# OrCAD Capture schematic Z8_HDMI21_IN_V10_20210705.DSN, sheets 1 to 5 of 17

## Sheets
1 PAGE06-HDMI21 IN: size Custom
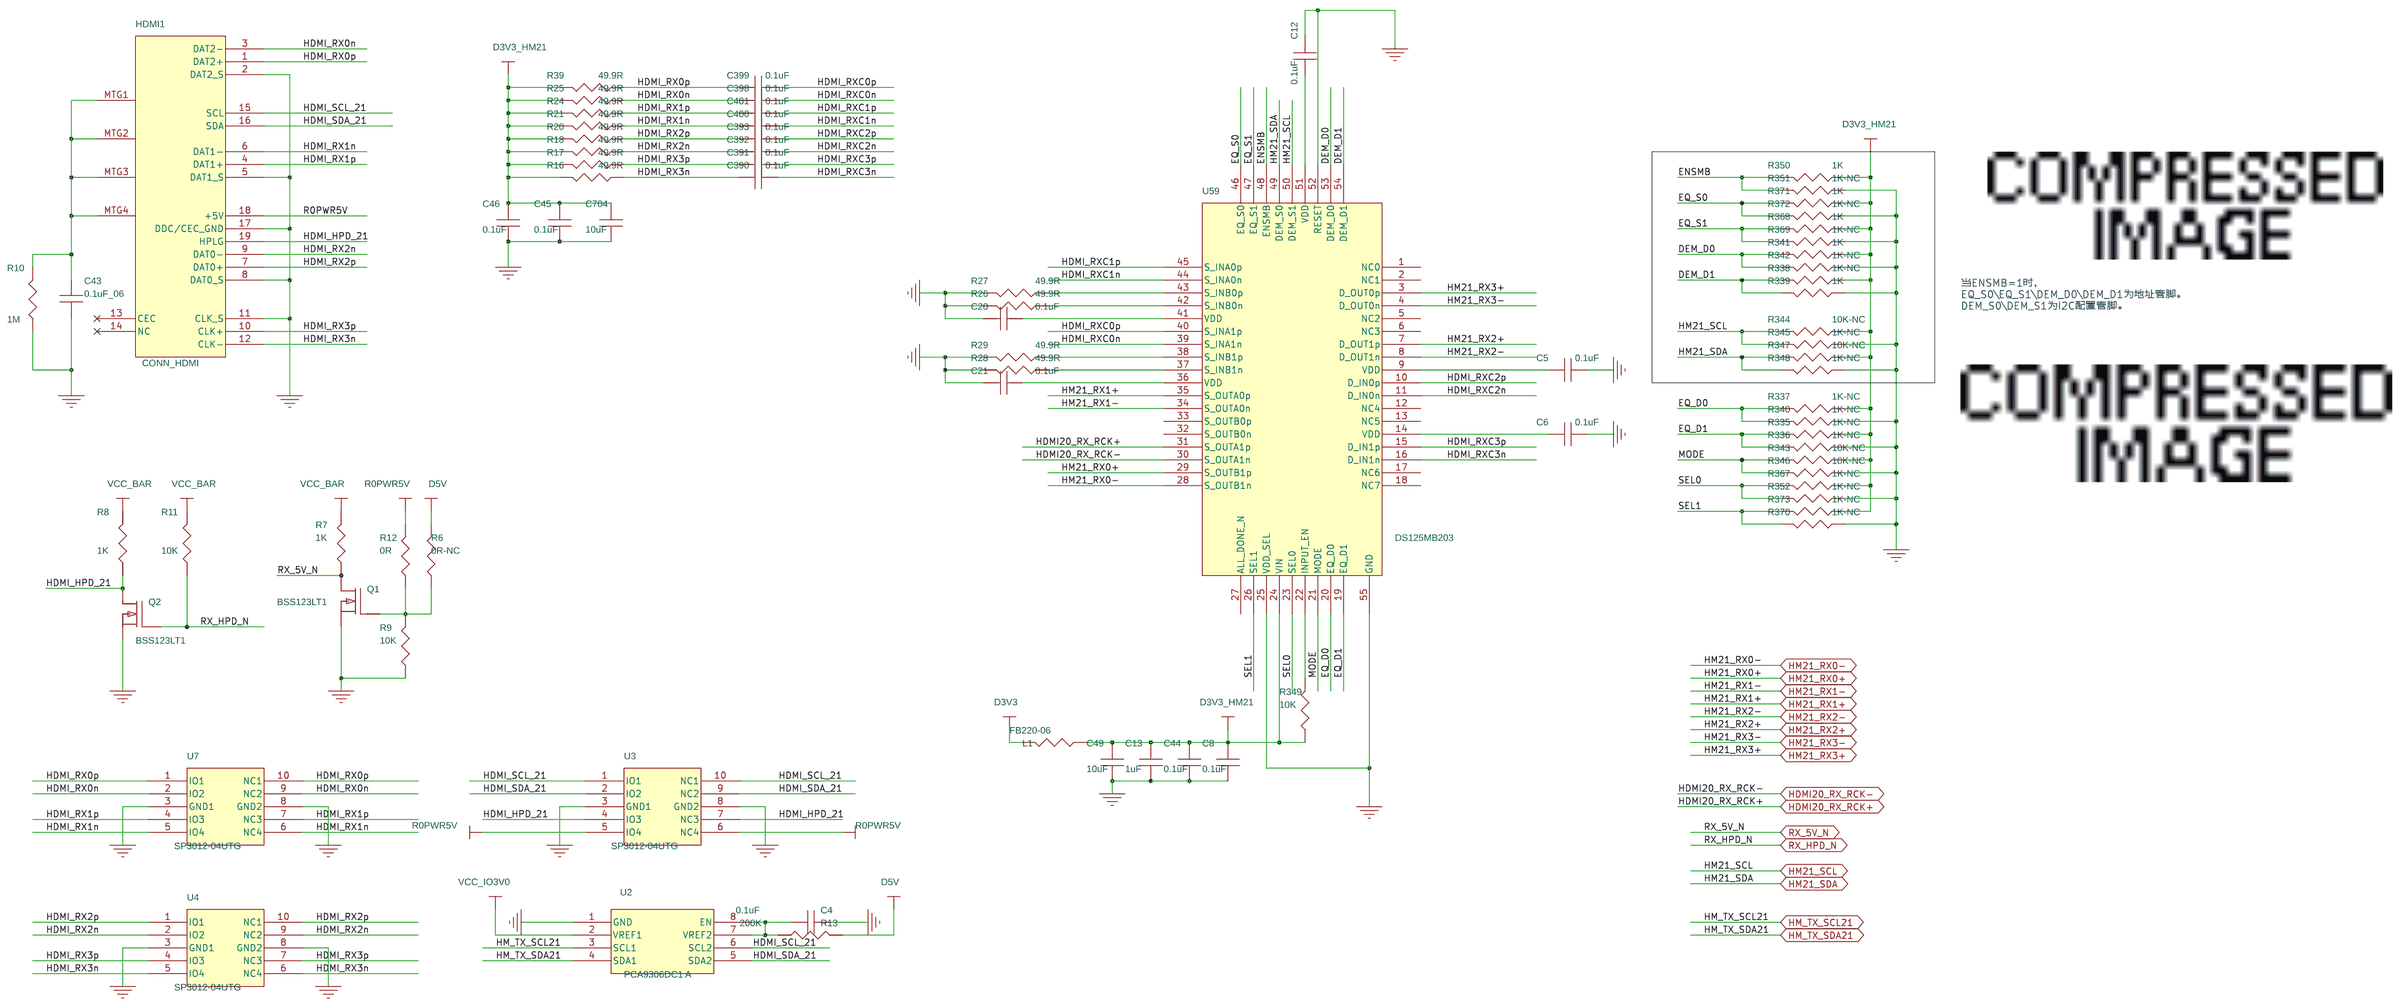
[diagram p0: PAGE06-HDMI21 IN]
2 PAGE10-HDMI20 OUT4: size Custom
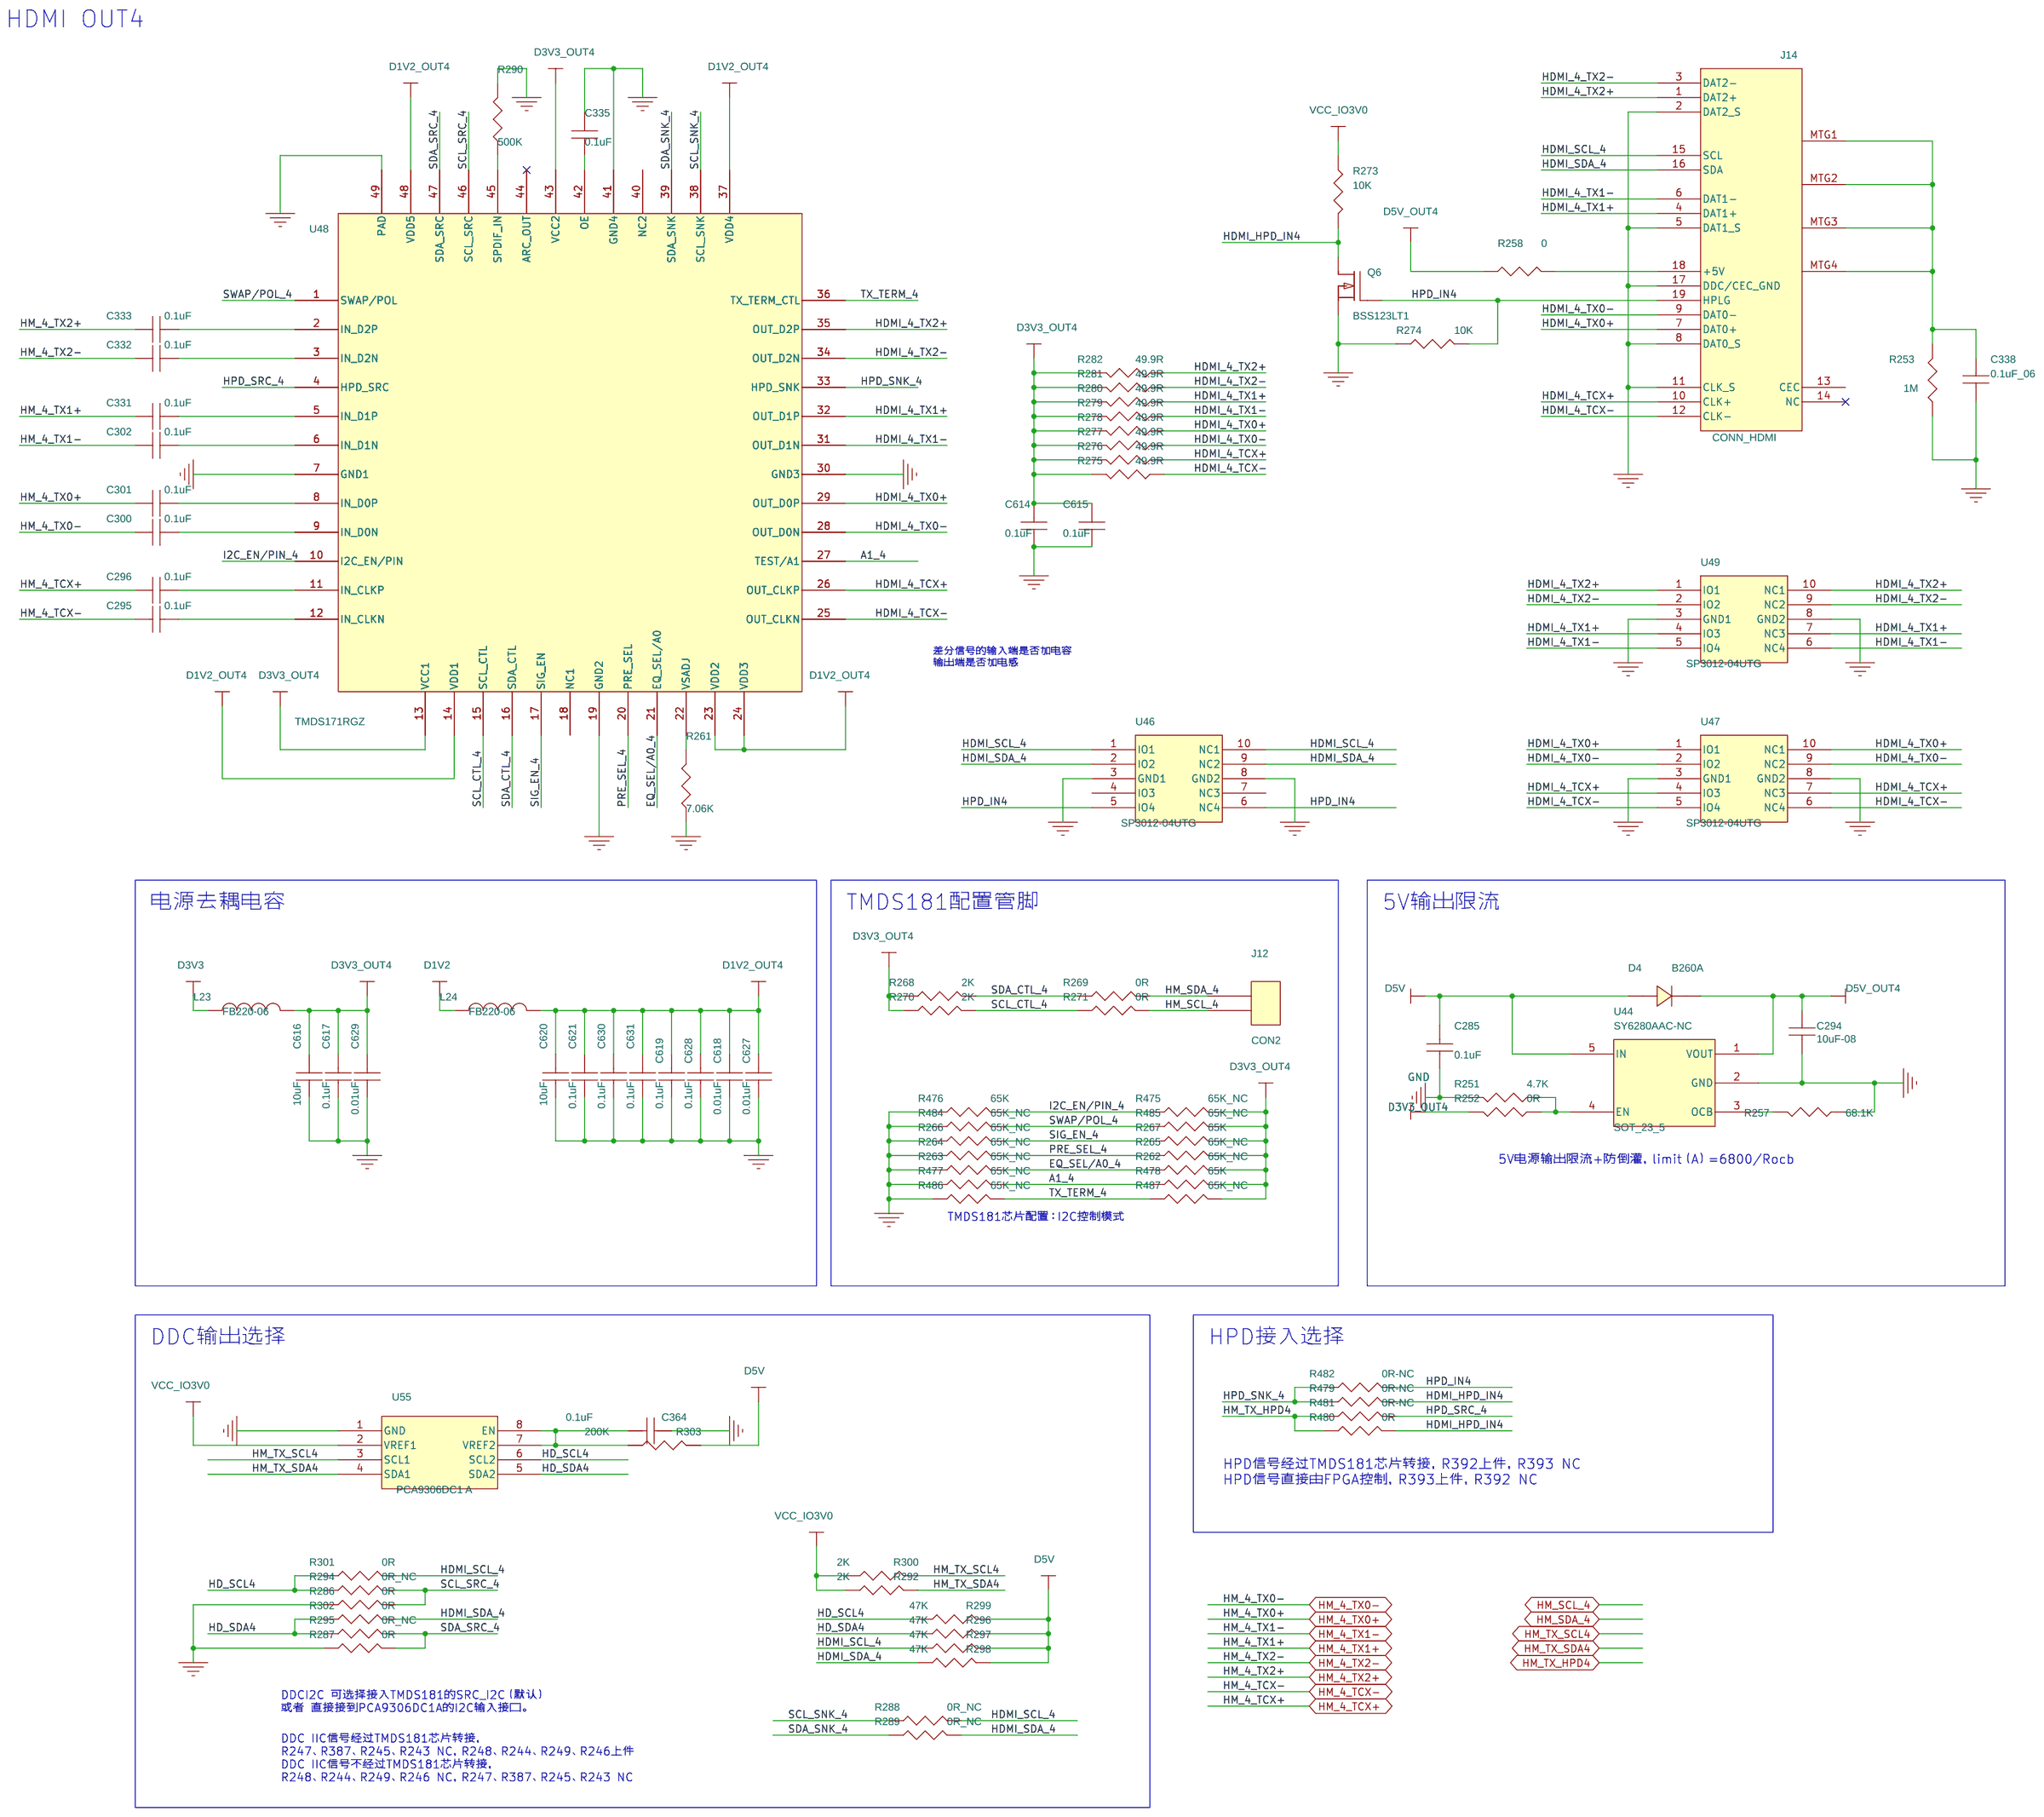
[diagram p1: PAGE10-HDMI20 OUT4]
3 PAGE09-HDMI20 OUT3: size Custom
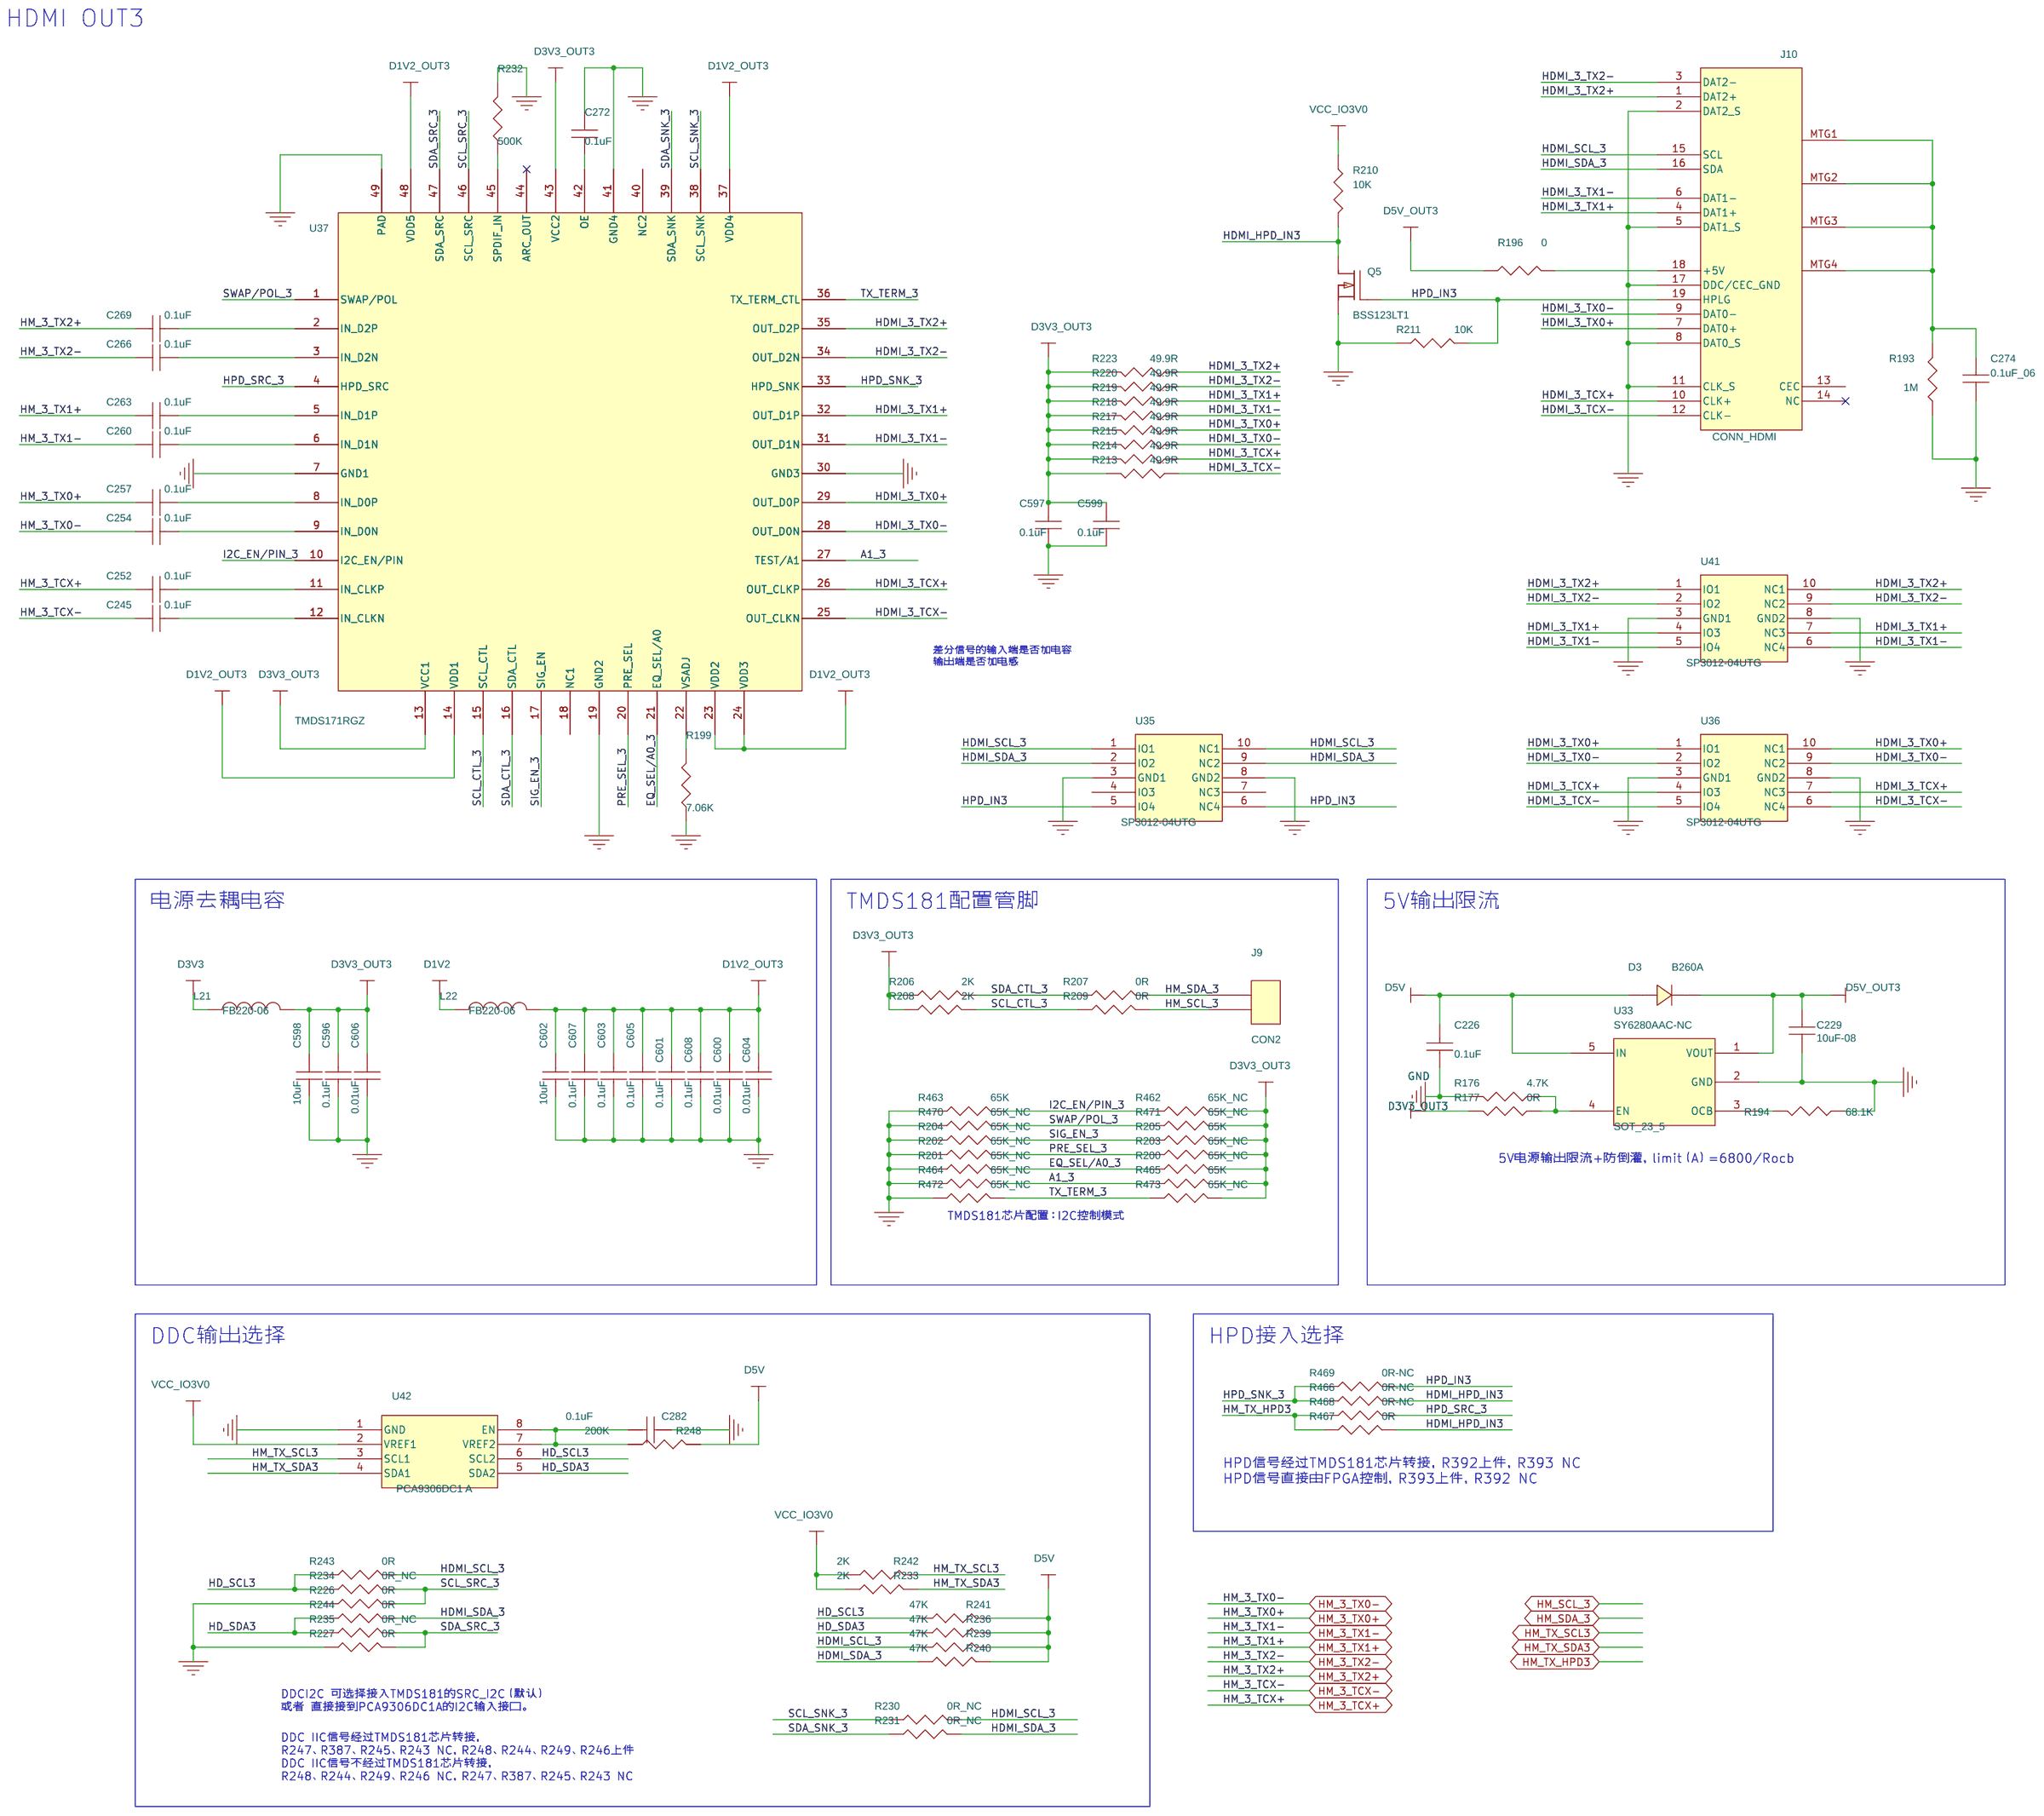
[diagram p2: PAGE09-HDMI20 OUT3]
4 PAGE12-10AX032-(2K&2J): size C
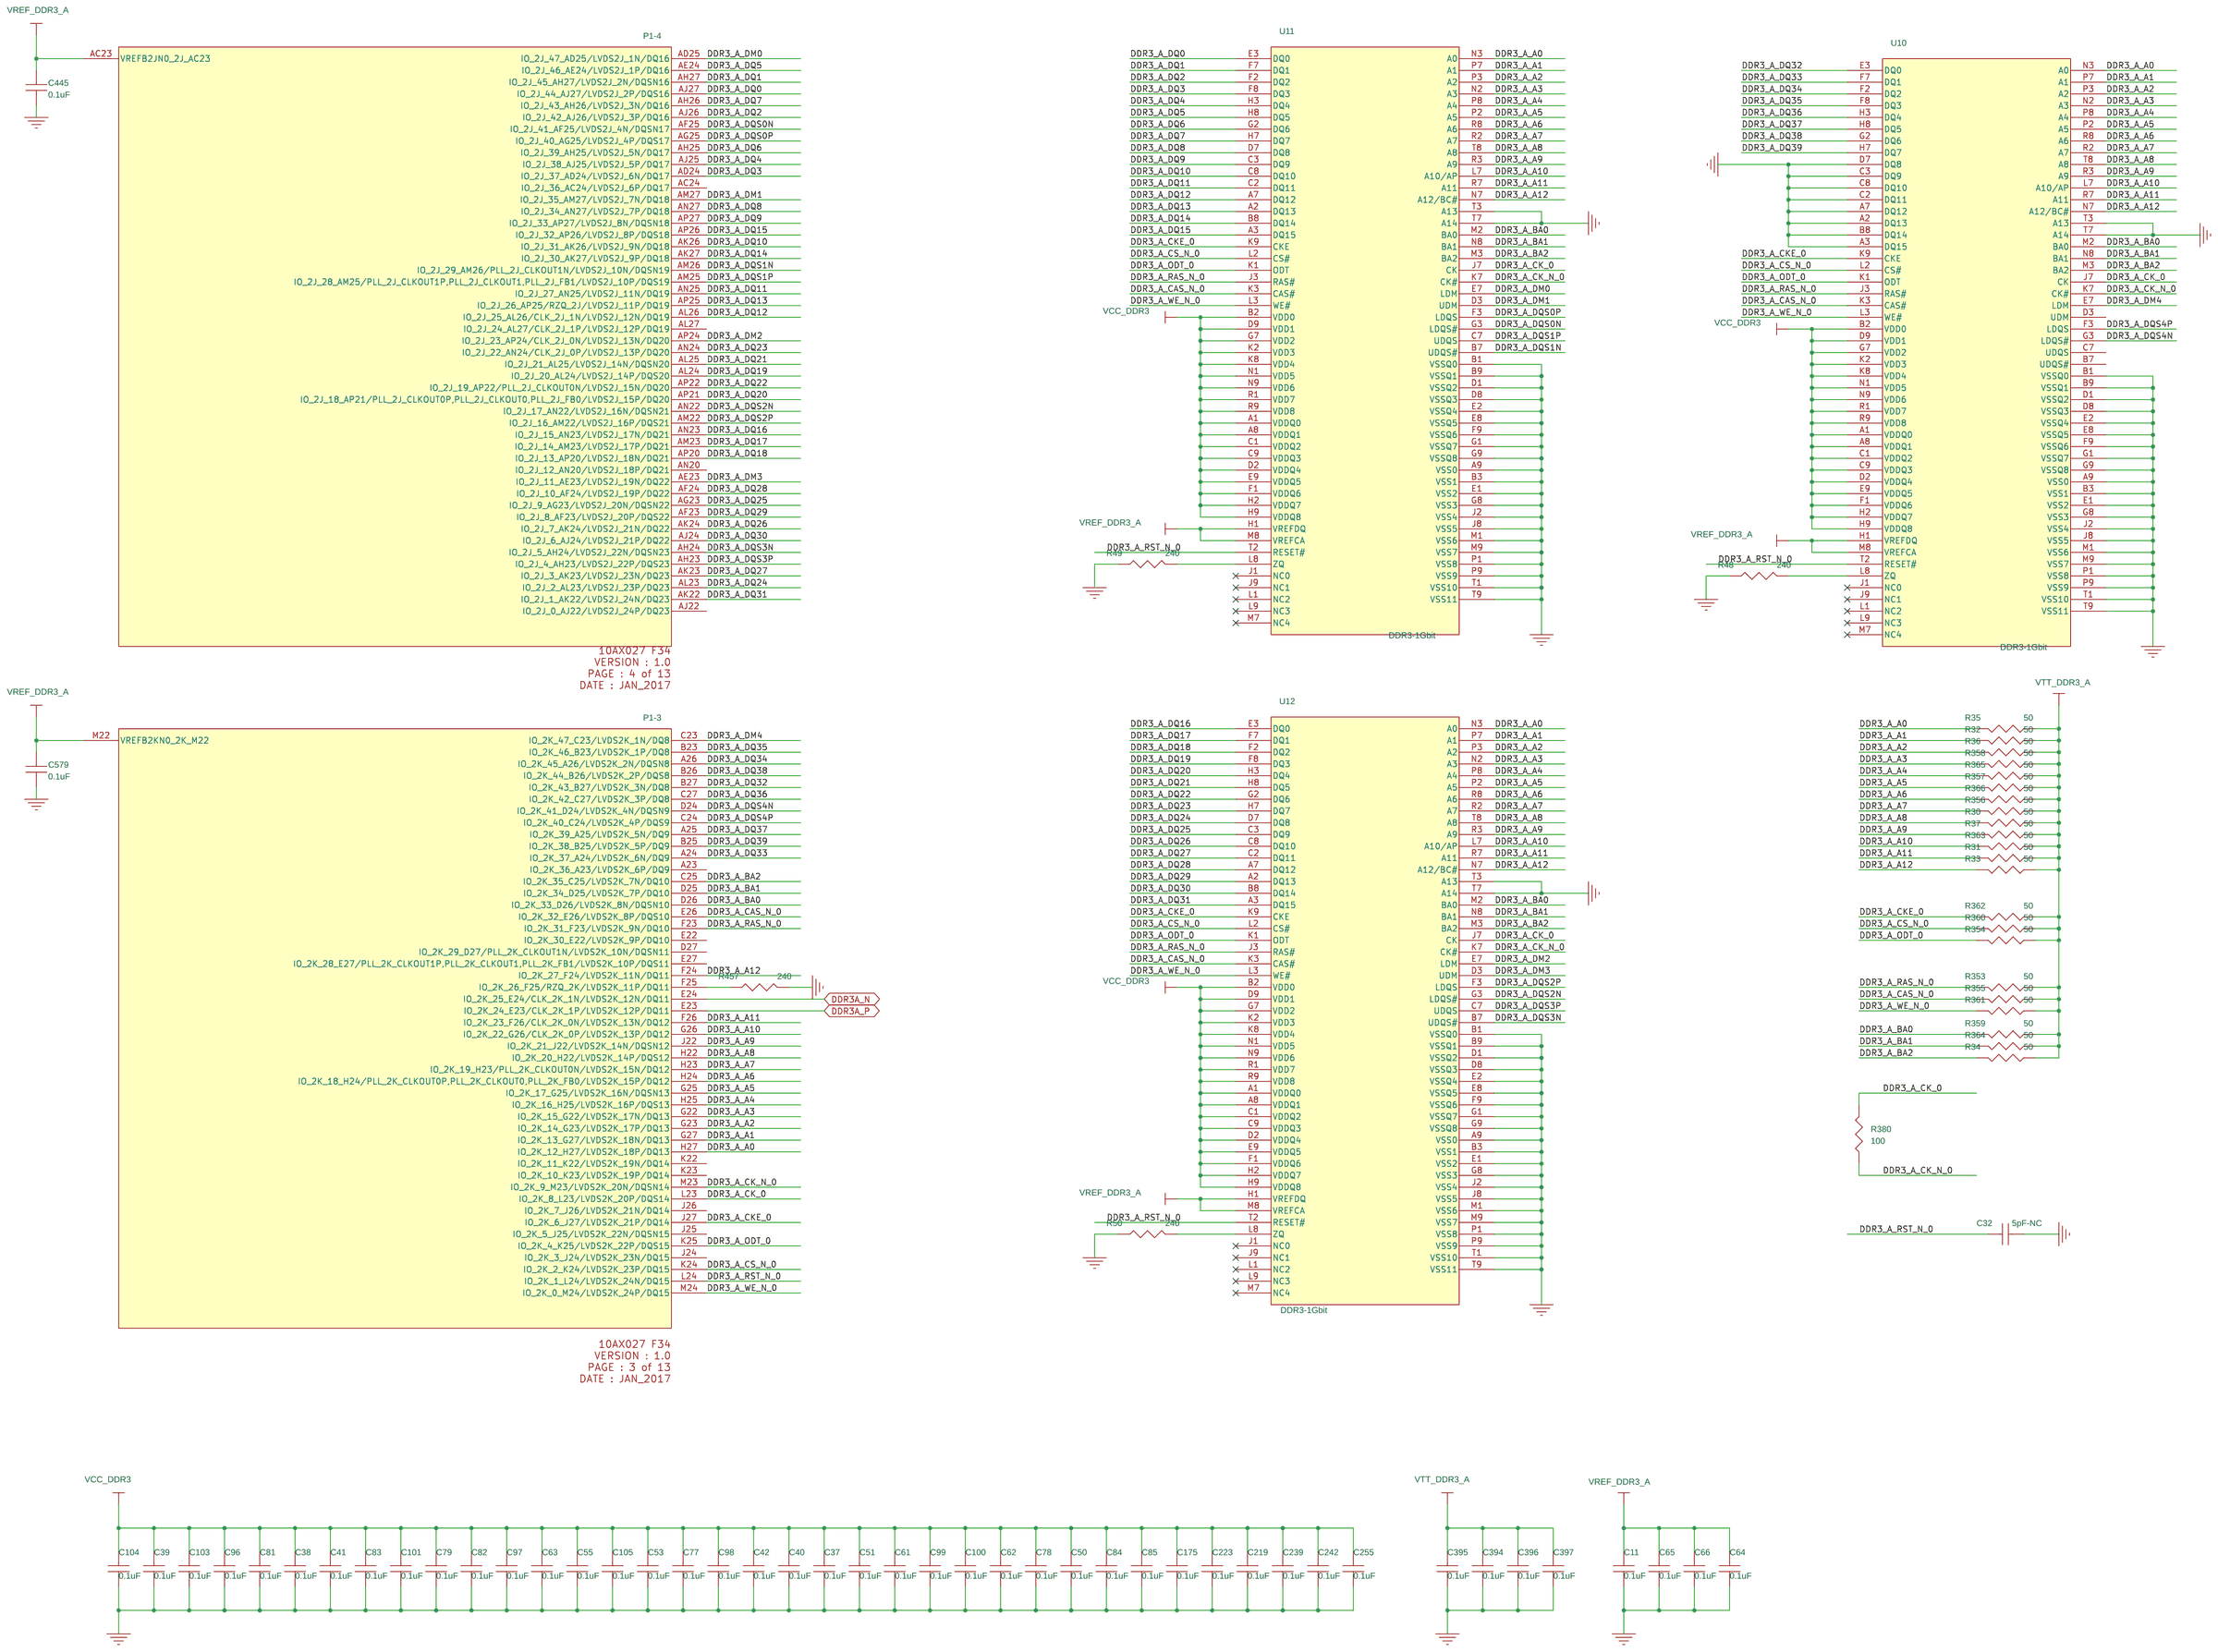
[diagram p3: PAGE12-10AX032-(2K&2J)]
5 PAGE11-10AX032-(GX): size D
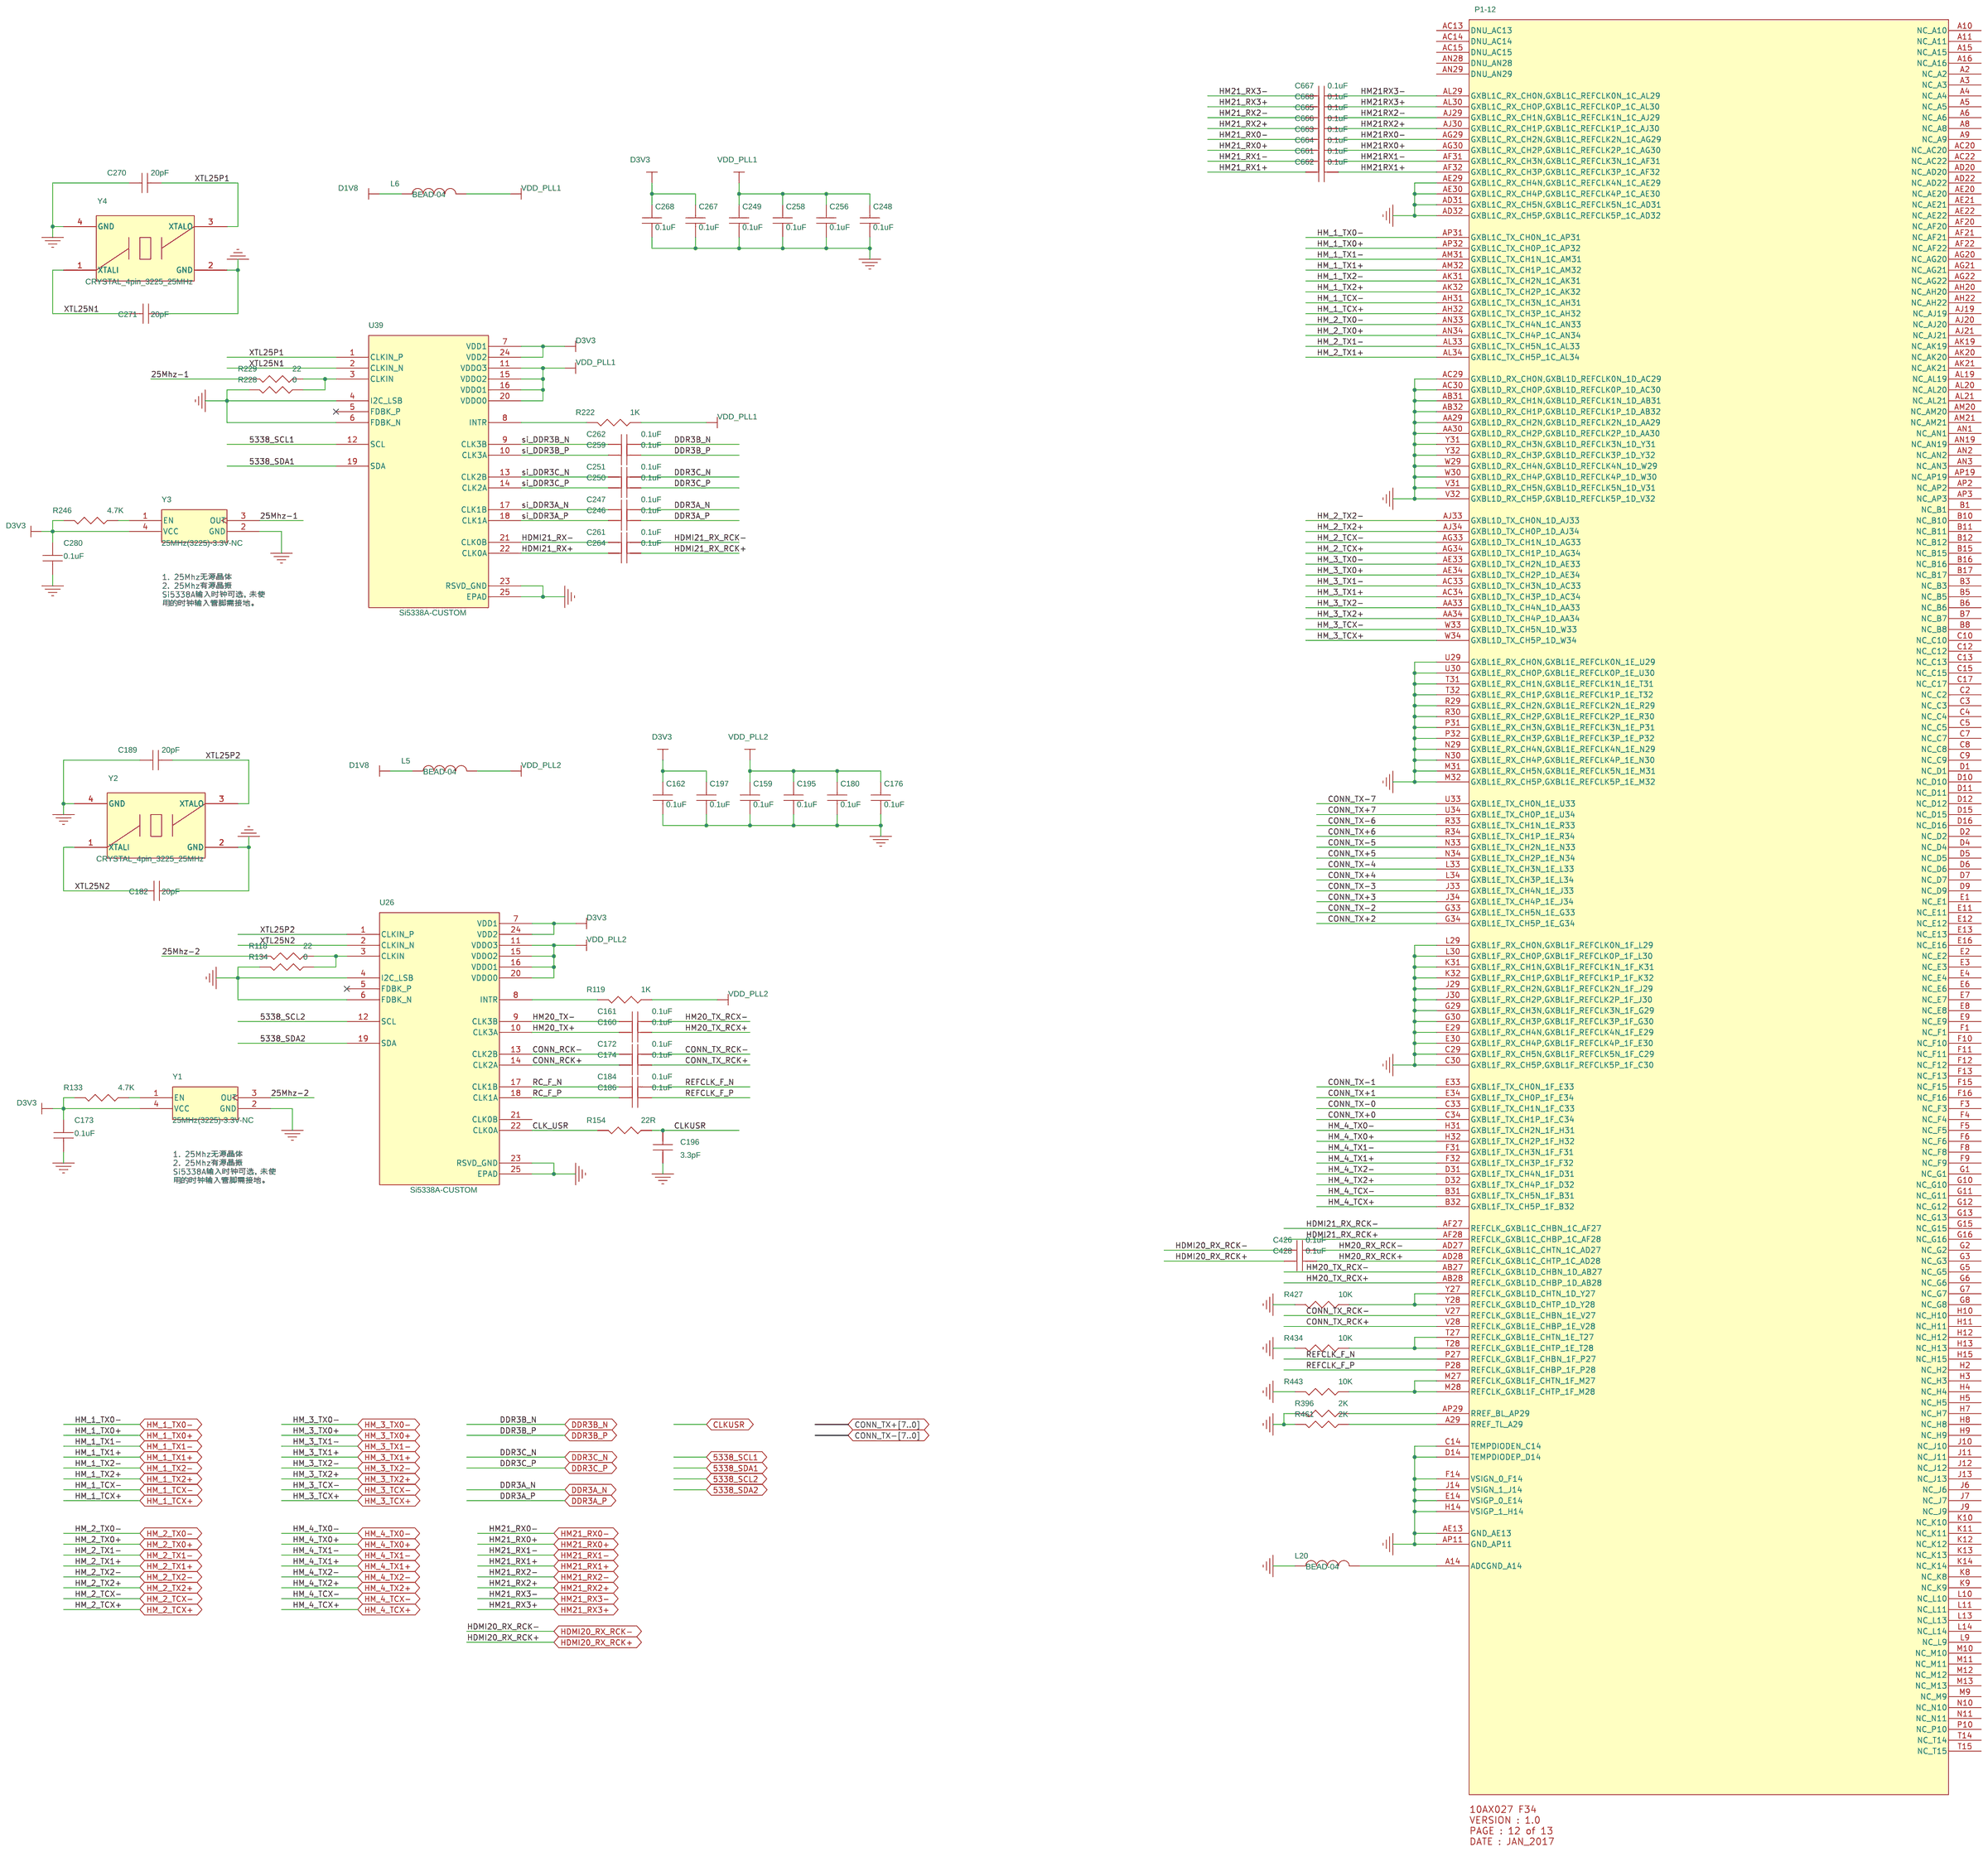
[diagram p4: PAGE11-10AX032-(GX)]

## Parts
sheet PAGE06-HDMI21 IN
C4  0.1uF  [C0402]
C5  0.1uF  [C0402]
C6  0.1uF  [C0402]
C8  0.1uF  [C0402]
C12  0.1uF  [C0402]
C13  1uF  [C0402]
C20  0.1uF  [C0402]
C21  0.1uF  [C0402]
C43  0.1uF_06  [C0402]
C44  0.1uF  [C0402]
C45  0.1uF  [C0402]
C46  0.1uF  [C0402]
C49  10uF  [C0402]
C390  0.1uF  [C0402-8]
C391  0.1uF  [C0402-8]
C392  0.1uF  [C0402-8]
C393  0.1uF  [C0402-8]
C398  0.1uF  [C0402-8]
C399  0.1uF  [C0402-8]
C400  0.1uF  [C0402-8]
C401  0.1uF  [C0402-8]
C704  10uF  [C0402]
HDMI1  CONN_HDMI  [hdmi]
L1  FB220-06  [R0603]
Q1  BSS123LT1  [SOT-23]
Q2  BSS123LT1  [SOT-23]
R6  0R-NC  [R0402]
R7  1K  [R0402]
R8  1K  [R0402]
R9  10K  [R0402]
R10  1M  [R0402]
R11  10K  [R0402]
R12  0R  [R0402]
R13  200K  [R0402]
R16  49.9R  [R0402]
R17  49.9R  [R0402]
R18  49.9R  [R0402]
R20  49.9R  [R0402]
R21  49.9R  [R0402]
R24  49.9R  [R0402]
R25  49.9R  [R0402]
R26  49.9R  [R0402]
R27  49.9R  [R0402]
R28  49.9R  [R0402]
R29  49.9R  [R0402]
R39  49.9R  [R0402]
R335  1K-NC  [R0402]
R336  1K-NC  [R0402]
R337  1K-NC  [R0402]
R338  1K-NC  [R0402]
R339  1K  [R0402]
R340  1K-NC  [R0402]
R341  1K  [R0402]
R342  1K-NC  [R0402]
R343  10K-NC  [R0402]
R344  10K-NC  [R0402]
R345  1K-NC  [R0402]
R346  10K-NC  [R0402]
R347  10K-NC  [R0402]
R348  1K-NC  [R0402]
R349  10K  [R0402]
R350  1K  [R0402]
R351  1K-NC  [R0402]
R352  1K-NC  [R0402]
R367  1K-NC  [R0402]
R368  1K  [R0402]
R369  1K-NC  [R0402]
R370  1K-NC  [R0402]
R371  1K  [R0402]
R372  1K-NC  [R0402]
R373  1K-NC  [R0402]
U2  PCA9306DC1 A  [SOIC8_E0D65_4D55XE3D15]
U3  SP3012-04UTG  [uDFN-10]
U4  SP3012-04UTG  [uDFN-10]
U7  SP3012-04UTG  [uDFN-10]
U59  DS125MB203  [DS125MB203]
sheet PAGE09-HDMI20 OUT3
C226  0.1uF  [C0402]
C229  10uF-08  [C0805]
C245  0.1uF  [C0402]
C252  0.1uF  [C0402]
C254  0.1uF  [C0402]
C257  0.1uF  [C0402]
C260  0.1uF  [C0402]
C263  0.1uF  [C0402]
C266  0.1uF  [C0402]
C269  0.1uF  [C0402]
C272  0.1uF  [C0402]
C274  0.1uF_06  [C0402]
C282  0.1uF  [C0402]
C596  0.1uF  [C0402]
C597  0.1uF  [C0402]
C598  10uF  [C0402]
C599  0.1uF  [C0402]
C600  0.01uF  [C0402]
C601  0.1uF  [C0402]
C602  10uF  [C0402]
C603  0.1uF  [C0402]
C604  0.01uF  [C0402]
C605  0.1uF  [C0402]
C606  0.01uF  [C0402]
C607  0.1uF  [C0402]
C608  0.1uF  [C0402]
D3  B260A  [SMA_DIODES]
J9  CON2  [CON2]
J10  CONN_HDMI  [hdmi]
L21  FB220-06  [my_0603_res]
L22  FB220-06  [my_0603_res]
Q5  BSS123LT1  [SOT-23]
R176  4.7K  [R0402]
R177  0R  [R0402]
R193  1M  [R0402]
R194  68.1K  [R0402]
R196  0  [R0402]
R199  7.06K  [R0402]
R200  65K_NC  [R0402]
R201  65K_NC  [R0402]
R202  65K_NC  [R0402]
R203  65K_NC  [R0402]
R204  65K_NC  [R0402]
R205  65K  [R0402]
R206  2K  [R0402]
R207  0R  [R0402]
R208  2K  [R0402]
R209  0R  [R0402]
R210  10K  [R0402]
R211  10K  [R0402]
R213  49.9R  [R0402]
R214  49.9R  [R0402]
R215  49.9R  [R0402]
R217  49.9R  [R0402]
R218  49.9R  [R0402]
R219  49.9R  [R0402]
R220  49.9R  [R0402]
R223  49.9R  [R0402]
R226  0R  [R0402]
R227  0R  [R0402]
R230  0R_NC  [R0402]
R231  0R_NC  [R0402]
R232  500K  [R0402]
R233  2K  [R0402]
R234  0R_NC  [R0402]
R235  0R_NC  [R0402]
R236  47K  [R0402]
R239  47K  [R0402]
R240  47K  [R0402]
R241  47K  [R0402]
R242  2K  [R0402]
R243  0R  [R0402]
R244  0R  [R0402]
R248  200K  [R0402]
R462  65K_NC  [R0402]
R463  65K  [R0402]
R464  65K_NC  [R0402]
R465  65K  [R0402]
R466  0R-NC  [R0402]
R467  0R  [R0402]
R468  0R-NC  [R0402]
R469  0R-NC  [R0402]
R470  65K_NC  [R0402]
R471  65K_NC  [R0402]
R472  65K_NC  [R0402]
R473  65K_NC  [R0402]
U33  SY6280AAC-NC  [SOT_23_5]
U35  SP3012-04UTG  [uDFN-10]
U36  SP3012-04UTG  [uDFN-10]
U37  TMDS171RGZ  [QFN48_TMDS181]
U41  SP3012-04UTG  [uDFN-10]
U42  PCA9306DC1 A  [SOIC8_E0D65_4D55XE3D15]
sheet PAGE10-HDMI20 OUT4
C285  0.1uF  [C0402]
C294  10uF-08  [C0805]
C295  0.1uF  [C0402]
C296  0.1uF  [C0402]
C300  0.1uF  [C0402]
C301  0.1uF  [C0402]
C302  0.1uF  [C0402]
C331  0.1uF  [C0402]
C332  0.1uF  [C0402]
C333  0.1uF  [C0402]
C335  0.1uF  [C0402]
C338  0.1uF_06  [C0402]
C364  0.1uF  [C0402]
C614  0.1uF  [C0402]
C615  0.1uF  [C0402]
C616  10uF  [C0402]
C617  0.1uF  [C0402]
C618  0.01uF  [C0402]
C619  0.1uF  [C0402]
C620  10uF  [C0402]
C621  0.1uF  [C0402]
C627  0.01uF  [C0402]
C628  0.1uF  [C0402]
C629  0.01uF  [C0402]
C630  0.1uF  [C0402]
C631  0.1uF  [C0402]
D4  B260A  [SMA_DIODES]
J12  CON2  [CON2]
J14  CONN_HDMI  [hdmi]
L23  FB220-06  [my_0603_res]
L24  FB220-06  [my_0603_res]
Q6  BSS123LT1  [SOT-23]
R251  4.7K  [R0402]
R252  0R  [R0402]
R253  1M  [R0402]
R257  68.1K  [R0402]
R258  0  [R0402]
R261  7.06K  [R0402]
R262  65K_NC  [R0402]
R263  65K_NC  [R0402]
R264  65K_NC  [R0402]
R265  65K_NC  [R0402]
R266  65K_NC  [R0402]
R267  65K  [R0402]
R268  2K  [R0402]
R269  0R  [R0402]
R270  2K  [R0402]
R271  0R  [R0402]
R273  10K  [R0402]
R274  10K  [R0402]
R275  49.9R  [R0402]
R276  49.9R  [R0402]
R277  49.9R  [R0402]
R278  49.9R  [R0402]
R279  49.9R  [R0402]
R280  49.9R  [R0402]
R281  49.9R  [R0402]
R282  49.9R  [R0402]
R286  0R  [R0402]
R287  0R  [R0402]
R288  0R_NC  [R0402]
R289  0R_NC  [R0402]
R290  500K  [R0402]
R292  2K  [R0402]
R294  0R_NC  [R0402]
R295  0R_NC  [R0402]
R296  47K  [R0402]
R297  47K  [R0402]
R298  47K  [R0402]
R299  47K  [R0402]
R300  2K  [R0402]
R301  0R  [R0402]
R302  0R  [R0402]
R303  200K  [R0402]
R475  65K_NC  [R0402]
R476  65K  [R0402]
R477  65K_NC  [R0402]
R478  65K  [R0402]
R479  0R-NC  [R0402]
R480  0R  [R0402]
R481  0R-NC  [R0402]
R482  0R-NC  [R0402]
R484  65K_NC  [R0402]
R485  65K_NC  [R0402]
R486  65K_NC  [R0402]
R487  65K_NC  [R0402]
U44  SY6280AAC-NC  [SOT_23_5]
U46  SP3012-04UTG  [uDFN-10]
U47  SP3012-04UTG  [uDFN-10]
U48  TMDS171RGZ  [QFN48_TMDS181]
U49  SP3012-04UTG  [uDFN-10]
U55  PCA9306DC1 A  [SOIC8_E0D65_4D55XE3D15]
sheet PAGE11-10AX032-(GX)
C159  0.1uF  [C0402]
C160  0.1uF  [C0402]
C161  0.1uF  [C0402]
C162  0.1uF  [C0402]
C172  0.1uF  [C0402]
C173  0.1uF  [C0402]
C174  0.1uF  [C0402]
C176  0.1uF  [C0402]
C180  0.1uF  [C0402]
C182  20pF  [C0402]
C184  0.1uF  [C0402]
C186  0.1uF  [C0402]
C189  20pF  [C0402]
C195  0.1uF  [C0402]
C196  3.3pF  [C0402]
C197  0.1uF  [C0402]
C246  0.1uF  [C0402]
C247  0.1uF  [C0402]
C248  0.1uF  [C0402]
C249  0.1uF  [C0402]
C250  0.1uF  [C0402]
C251  0.1uF  [C0402]
C256  0.1uF  [C0402]
C258  0.1uF  [C0402]
C259  0.1uF  [C0402]
C261  0.1uF  [C0402]
C262  0.1uF  [C0402]
C264  0.1uF  [C0402]
C267  0.1uF  [C0402]
C268  0.1uF  [C0402]
C270  20pF  [C0402]
C271  20pF  [C0402]
C280  0.1uF  [C0402]
C426  0.1uF  [C0402-8]
C428  0.1uF  [C0402-8]
C661  0.1uF  [C0402-8]
C662  0.1uF  [C0402-8]
C663  0.1uF  [C0402-8]
C664  0.1uF  [C0402-8]
C665  0.1uF  [C0402-8]
C666  0.1uF  [C0402-8]
C667  0.1uF  [C0402-8]
C668  0.1uF  [C0402-8]
L5  BEAD-04  [R0402]
L6  BEAD-04  [R0402]
L20  BEAD-04  [R0402]
R118  22  [R0402]
R119  1K  [R0402]
R133  4.7K  [R0402]
R134  0  [R0402]
R154  22R  [R0402]
R222  1K  [R0402]
R228  0  [R0402]
R229  22  [R0402]
R246  4.7K  [R0402]
R396  2K  [C0402-8]
R427  10K  [C0402-8]
R434  10K  [C0402-8]
R443  10K  [C0402-8]
R461  2K  [C0402-8]
U26  Si5338A-CUSTOM  [QFN24]
U39  Si5338A-CUSTOM  [QFN24]
Y1  25MHz(3225)-3.3V-NC  [XTAL_ABM8]
Y2  CRYSTAL_4pin_3225_25MHz  [XTAL_ABM8]
Y3  25MHz(3225)-3.3V-NC  [XTAL_ABM8]
Y4  CRYSTAL_4pin_3225_25MHz  [XTAL_ABM8]
sheet PAGE12-10AX032-(2K&2J)
C11  0.1uF  [C0402]
C32  5pF-NC  [C0402]
C37  0.1uF  [C0402]
C38  0.1uF  [C0402]
C39  0.1uF  [C0402]
C40  0.1uF  [C0402]
C41  0.1uF  [C0402]
C42  0.1uF  [C0402]
C50  0.1uF  [C0402]
C51  0.1uF  [C0402]
C53  0.1uF  [C0402]
C55  0.1uF  [C0402]
C61  0.1uF  [C0402]
C62  0.1uF  [C0402]
C63  0.1uF  [C0402]
C64  0.1uF  [C0402]
C65  0.1uF  [C0402]
C66  0.1uF  [C0402]
C77  0.1uF  [C0402]
C78  0.1uF  [C0402]
C79  0.1uF  [C0402]
C81  0.1uF  [C0402]
C82  0.1uF  [C0402]
C83  0.1uF  [C0402]
C84  0.1uF  [C0402]
C85  0.1uF  [C0402]
C96  0.1uF  [C0402]
C97  0.1uF  [C0402]
C98  0.1uF  [C0402]
C99  0.1uF  [C0402]
C100  0.1uF  [C0402]
C101  0.1uF  [C0402]
C103  0.1uF  [C0402]
C104  0.1uF  [C0402]
C105  0.1uF  [C0402]
C175  0.1uF  [C0402]
C219  0.1uF  [C0402]
C223  0.1uF  [C0402]
C239  0.1uF  [C0402]
C242  0.1uF  [C0402]
C255  0.1uF  [C0402]
C394  0.1uF  [C0402]
C395  0.1uF  [C0402]
C396  0.1uF  [C0402]
C397  0.1uF  [C0402]
C445  0.1uF  [C0402-8]
C579  0.1uF  [C0402-8]
P1  10AX027 F34  [BGA1152_PAD18]  (sections -1,-10,-11,-12,-13,-2,-3,-4,-5,-6,-7,-8,-9)
R30  50  [R0402]
R31  50  [R0402]
R32  50  [R0402]
R33  50  [R0402]
R34  50  [R0402]
R35  50  [R0402]
R36  50  [R0402]
R37  50  [R0402]
R48  240  [R0402]
R49  240  [R0402]
R50  240  [R0402]
R353  50  [R0402]
R354  50  [R0402]
R355  50  [R0402]
R356  50  [R0402]
R357  50  [R0402]
R358  50  [R0402]
R359  50  [R0402]
R360  50  [R0402]
R361  50  [R0402]
R362  50  [R0402]
R363  50  [R0402]
R364  50  [R0402]
R365  50  [R0402]
R366  50  [R0402]
R380  100  [R0402]
R457  240  [C0402-8]
U10  DDR3-1Gbit  [fbga96-10x14]
U11  DDR3-1Gbit  [fbga96-10x14]
U12  DDR3-1Gbit  [fbga96-10x14]

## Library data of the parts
C4-C6 C8 C11-C13 C20 C21 C32 C37-C42 C44-C46 C49-C51 C53 C55 C61-C66 C77-C79 C81-C85 C96-C101 C103-C105 C173 C175 C219 C223 C226 C229 C239 C242 C245 C252 C254 C255 C257 C260 C263 C266 C269 C272 C280 C282 C285 C294-C296 C300-C302 C331-C333 C335 C364 C390-C401 C426 C428 C445 C579 C596-C608 C614-C621 C627-C631 C661-C668 C704 = CAP_NP
C43 C274 C338 = CAP_NP: ROOM: DVI; VOLTAGE: 25V
HDMI1 J10 J14 = CONN_HDMI_1
L1 R6-R13 R16-R18 R20 R21 R24-R37 R39 R48-R50 R176 R177 R193 R194 R196 R199-R211 R213-R215 R217-R220 R223 R226 R227 R230-R236 R239-R244 R248 R251-R253 R257 R258 R261-R271 R273-R282 R286-R290 R292 R294-R303 R335-R373 R380 R396 R427 R434 R443 R457 R461-R473 R475-R482 R484-R487 = R
Q1 Q2 Q5 Q6 = MFE825_0
U2 U42 U55 = PCA9306DC1_A
U3 U4 U7 U35 U36 U41 U46 U47 U49 = SP3012-04UTG
U59 = DS125MB203_0
D3 D4 = DIODE_0
J9 J12 = CON2
L5 L6 L20-L24 = L_0
U33 U44 = SWITCH_SY6280: Low Loss Power Distribution Switch; Created by: JJJ; Manufacturer: Silergy（矽力杰）; Manufacturer PN: SY6280AAC; Option: <option>; Part Type: Switch; Priority: A; RK PN: SY6280AAC
U37 U48 = DP159RGZ_0: SILKTEXT: 48 PIN RGZ, HSIO
C159-C162 C172 C174 C176 C180 C184 C186 C195 C197 C246-C251 C256 C258 C259 C261 C262 C264 C267 C268 = CAP: CAP - CERAMIC,  0.1UF 0402 25VDC Y5V; AGILE_LINK: http://sj-agile9app/Agile/PLMServlet?action=OpenEmailObject&classid=10000&objid=213459527; Item Num: P03-15057R; LIFECYCLE_PHASE: Active; Lead Free Status: Lead Free; MFR_LIFECYCLE: Active; Manufacturer: Murata; Manufacturer Part Num: GRM155F51E104ZA01D; Num Pins: 2; PART_SUBCLASS: CAPACITORS; Part Class: CAPACITORS; RATED_VOLTAGE: 25V; RoHS Compliant: RoHS Compliant; TOLERANCE: +80%/-20%
C182 C189 C270 C271 = CAP_0402_100pF_COG_50V: CAP,CER,C0G,0402,50V,10%,22PF; MANUFACTURER: VISHAY; ORDER#: VJ0402A220KXAA
C196 = CAP: CAP - CERAMIC,  0.1UF 0402 25VDC Y5V; AGILE_LINK: http://sj-agile9app/Agile/PLMServlet?action=OpenEmailObject&classid=10000&objid=213459527; CAPACITANCE: 0.1uF; Item Num: P03-15057R; LIFECYCLE_PHASE: Active; Lead Free Status: Lead Free; MFR_LIFECYCLE: Active; Manufacturer: Murata; Manufacturer Part Num: GRM155F51E104ZA01D; Num Pins: 2; PART_SUBCLASS: CAPACITORS; Part Class: CAPACITORS; RATED_VOLTAGE: 25V; RoHS Compliant: RoHS Compliant; TOLERANCE: +80%/-20%
R118 R119 R134 R154 R222 R228 R229 = RESISTOR: RES,4.70K OHMS,1.0%,1/16W,0402; AGILE_LINK: http://sj-agile9app/Agile/PLMServlet?action=OpenEmailObject&classid=10000&objid=146753272; Item Num: P02-11384R; LIFECYCLE_PHASE: Active; Lead Free Status: No; MFR_LIFECYCLE: Active; Manufacturer: Vishay; Manufacturer Part Num: CRCW04024K70FKED; Num Pins: 2; PART_SUBCLASS: RESISTORS; POWER: 1/16W; RESISTANCE: 4.7K; RoHS Compliant: Yes; TOLERANCE: +/-1%
R133 R246 = RESISTOR: RES,4.70K OHMS,1.0%,1/16W,0402; AGILE_LINK: http://sj-agile9app/Agile/PLMServlet?action=OpenEmailObject&classid=10000&objid=146753272; Item Num: P02-11384R; LIFECYCLE_PHASE: Active; Lead Free Status: No; MFR_LIFECYCLE: Active; Manufacturer: Vishay; Manufacturer Part Num: CRCW04024K70FKED; Num Pins: 2; PART_SUBCLASS: RESISTORS; POWER: 1/16W; RoHS Compliant: Yes; TOLERANCE: +/-1%
U26 U39 = Si5338A_0: IC - PROG, 1.8V LVDS QUAD CLOCK, 270MHz, 644.53125MHz, 644.53125MHz, 133.33MHz DEFAULTS, I2C 7A; Item Num: P01-17874R; Lead Free Status: Yes; MFR_LIFECYCLE: Active; Manufacturer: Silicon Laboratories; Manufacturer Part Num: Si5338A-B02498-GM; Num Pins: 25; Part Class: ICS; RoHS Compliant: YES
Y1 Y3 = OSC4_SM_0
Y2 Y4 = CRYSTAL_4pin_3225
P1 = 10AX027_F34_2
U10-U12 = DDR3-512MB

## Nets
D1V2: L22.2 L24.2 ; also on sheet 6 7 10
D1V2_OUT3: C600.2 C601.2 C602.2 C603.2 C604.2 C605.2 C607.2 C608.2 L22.1 U37.14(VDD1) U37.23(VDD2) U37.24(VDD3) U37.37(VDD4) U37.48(VDD5)
D1V2_OUT4: C618.2 C619.2 C620.2 C621.2 C627.2 C628.2 C630.2 C631.2 L24.1 U48.14(VDD1) U48.23(VDD2) U48.24(VDD3) U48.37(VDD4) U48.48(VDD5)
D1V8: L5.2 L6.2 ; also on sheet 10
D3V3: C162.1 C173.1 C197.1 C267.1 C268.1 C280.1 L1.1 L21.2 L23.2 R133.1 R246.1 U26.7(VDD1) U26.24(VDD2) U39.7(VDD1) U39.24(VDD2) Y1.4(VCC) Y3.4(VCC) ; also on sheet 6 7 8 10 17
D3V3_HM21: C8.2 C13.2 C44.2 C45.2 C46.2 C49.2 C704.2 L1.2 R16.1 R17.1 R18.1 R20.1 R21.1 R24.1 R25.1 R39.1 R335.2 R337.2 R338.2 R341.2 R343.2 R344.2 R347.2 R349.2 R350.2 R367.2 R368.2 R371.2 R373.2 U59.24(VIN)
D3V3_OUT3: C596.2 C597.2 C598.2 C599.2 C606.2 L21.1 R177.2 R200.1 R203.1 R205.1 R206.1 R208.1 R213.1 R214.1 R215.1 R217.1 R218.1 R219.1 R220.1 R223.1 R462.1 R465.1 R471.1 R473.1 U37.13(VCC1) U37.43(VCC2)
D3V3_OUT4: C614.2 C615.2 C616.2 C617.2 C629.2 L23.1 R252.2 R262.1 R265.1 R267.1 R268.1 R270.1 R275.1 R276.1 R277.1 R278.1 R279.1 R280.1 R281.1 R282.1 R475.1 R478.1 R485.1 R487.1 U48.13(VCC1) U48.43(VCC2)
D5V: C226.2 C285.2 D3.2(A) D4.2(A) R6.1 R8.1 R13.2 R236.2 R239.2 R240.2 R241.2 R248.2 R296.2 R297.2 R298.2 R299.2 R303.2 U33.5(IN) U44.5(IN) ; also on sheet 6 7 10
D5V_OUT3: C229.1 D3.1(K) R196.2 U33.1(VOUT)
D5V_OUT4: C294.1 D4.1(K) R258.2 U44.1(VOUT)
GND: C4.1 C5.2 C6.2 C8.1 C11.2 C12.2 C13.1 C20.2 C21.2 C32.2 C37.2 C38.2 C39.2 C40.2 C41.2 C42.2 C43.2 C44.1 C45.1 C46.1 C49.1 C50.2 C51.2 C53.2 C55.2 C61.2 C62.2 C63.2 C64.2 C65.2 C66.2 C77.2 C78.2 C79.2 C81.2 C82.2 C83.2 C84.2 C85.2 C96.2 C97.2 C98.2 C99.2 C100.2 C101.2 C103.2 C104.2 C105.2 C159.2 C162.2 C173.2 C175.2 C176.2 C180.2 C182.1 C189.1 C195.2 C196.1 C197.2 C219.2 C223.2 C226.1 C229.2 C239.2 C242.2 C248.2 C249.2 C255.2 C256.2 C258.2 C267.2 C268.2 C270.1 C271.1 C272.2 C274.2 C280.2 C282.1 C285.1 C294.2 C335.2 C338.2 C364.1 C394.2 C395.2 C396.2 C397.2 C445.2 C579.2 C596.1 C597.1 C598.1 C599.1 C600.1 C601.1 C602.1 C603.1 C604.1 C605.1 C606.1 C607.1 C608.1 C614.1 C615.1 C616.1 C617.1 C618.1 C619.1 C620.1 C621.1 C627.1 C628.1 C629.1 C630.1 C631.1 C704.1 HDMI1.2(DAT2_S) HDMI1.5(DAT1_S) HDMI1.8(DAT0_S) HDMI1.11(CLK_S) HDMI1.17(DDC/CEC_GND) J10.2(DAT2_S) J10.5(DAT1_S) J10.8(DAT0_S) J10.11(CLK_S) J10.17(DDC/CEC_GND) J14.2(DAT2_S) J14.5(DAT1_S) J14.8(DAT0_S) J14.11(CLK_S) J14.17(DDC/CEC_GND) L20.2 P1.AA29(GXBL1D_RX_CH2N,GXBL1D_REFCLK2N_1D) P1.AA30(GXBL1D_RX_CH2P,GXBL1D_REFCLK2P_1D) P1.AB31(GXBL1D_RX_CH1N,GXBL1D_REFCLK1N_1D) P1.AB32(GXBL1D_RX_CH1P,GXBL1D_REFCLK1P_1D) P1.AC29(GXBL1D_RX_CH0N,GXBL1D_REFCLK0N_1D) P1.AC30(GXBL1D_RX_CH0P,GXBL1D_REFCLK0P_1D) P1.AD31(GXBL1C_RX_CH5N,GXBL1C_REFCLK5N_1C) P1.AD32(GXBL1C_RX_CH5P,GXBL1C_REFCLK5P_1C) P1.AE13(GND) P1.AE29(GXBL1C_RX_CH4N,GXBL1C_REFCLK4N_1C) P1.AE30(GXBL1C_RX_CH4P,GXBL1C_REFCLK4P_1C) P1.AP11(GND) P1.C14(TEMPDIODEN) P1.C29(GXBL1F_RX_CH5N,GXBL1F_REFCLK5N_1F) P1.C30(GXBL1F_RX_CH5P,GXBL1F_REFCLK5P_1F) P1.D14(TEMPDIODEP) P1.E14(VSIGP_0) P1.E29(GXBL1F_RX_CH4N,GXBL1F_REFCLK4N_1F) P1.E30(GXBL1F_RX_CH4P,GXBL1F_REFCLK4P_1F) P1.F14(VSIGN_0) P1.G29(GXBL1F_RX_CH3N,GXBL1F_REFCLK3N_1F) P1.G30(GXBL1F_RX_CH3P,GXBL1F_REFCLK3P_1F) P1.H14(VSIGP_1) P1.J14(VSIGN_1) P1.J29(GXBL1F_RX_CH2N,GXBL1F_REFCLK2N_1F) P1.J30(GXBL1F_RX_CH2P,GXBL1F_REFCLK2P_1F) P1.K31(GXBL1F_RX_CH1N,GXBL1F_REFCLK1N_1F) P1.K32(GXBL1F_RX_CH1P,GXBL1F_REFCLK1P_1F) P1.L29(GXBL1F_RX_CH0N,GXBL1F_REFCLK0N_1F) P1.L30(GXBL1F_RX_CH0P,GXBL1F_REFCLK0P_1F) P1.M31(GXBL1E_RX_CH5N,GXBL1E_REFCLK5N_1E) P1.M32(GXBL1E_RX_CH5P,GXBL1E_REFCLK5P_1E) P1.N29(GXBL1E_RX_CH4N,GXBL1E_REFCLK4N_1E) P1.N30(GXBL1E_RX_CH4P,GXBL1E_REFCLK4P_1E) P1.P31(GXBL1E_RX_CH3N,GXBL1E_REFCLK3N_1E) P1.P32(GXBL1E_RX_CH3P,GXBL1E_REFCLK3P_1E) P1.R29(GXBL1E_RX_CH2N,GXBL1E_REFCLK2N_1E) P1.R30(GXBL1E_RX_CH2P,GXBL1E_REFCLK2P_1E) P1.T31(GXBL1E_RX_CH1N,GXBL1E_REFCLK1N_1E) P1.T32(GXBL1E_RX_CH1P,GXBL1E_REFCLK1P_1E) P1.U29(GXBL1E_RX_CH0N,GXBL1E_REFCLK0N_1E) P1.U30(GXBL1E_RX_CH0P,GXBL1E_REFCLK0P_1E) P1.V31(GXBL1D_RX_CH5N,GXBL1D_REFCLK5N_1D) P1.V32(GXBL1D_RX_CH5P,GXBL1D_REFCLK5P_1D) P1.W29(GXBL1D_RX_CH4N,GXBL1D_REFCLK4N_1D) P1.W30(GXBL1D_RX_CH4P,GXBL1D_REFCLK4P_1D) P1.Y31(GXBL1D_RX_CH3N,GXBL1D_REFCLK3N_1D) P1.Y32(GXBL1D_RX_CH3P,GXBL1D_REFCLK3P_1D) Q1.2(S) Q2.2(S) Q5.2(S) Q6.2(S) R9.2 R10.1 R26.1 R27.1 R28.1 R29.1 R48.1 R49.1 R50.1 R134.1 R176.2 R193.1 R194.1 R199.1 R201.2 R202.2 R204.2 R211.1 R226.2 R227.2 R228.1 R232.2 R251.2 R253.1 R257.1 R261.1 R263.2 R264.2 R266.2 R274.1 R286.2 R287.2 R290.2 R336.2 R339.2 R340.2 R342.2 R345.2 R346.2 R348.2 R351.2 R352.2 R369.2 R370.2 R372.2 R396.1 R427.1 R434.1 R443.1 R457.2 R461.1 R463.2 R464.2 R470.2 R472.2 R476.2 R477.2 R484.2 R486.2 U2.1(GND) U3.3(GND1) U3.8(GND2) U4.3(GND1) U4.8(GND2) U7.3(GND1) U7.8(GND2) U10.A2(DQ13) U10.A3(DQ15) U10.A7(DQ12) U10.A9(VSS0) U10.B1(VSSQ0) U10.B3(VSS1) U10.B8(DQ14) U10.B9(VSSQ1) U10.C2(DQ11) U10.C3(DQ9) U10.C8(DQ10) U10.D1(VSSQ2) U10.D7(DQ8) U10.D8(VSSQ3) U10.E1(VSS2) U10.E2(VSSQ4) U10.E8(VSSQ5) U10.F9(VSSQ6) U10.G1(VSSQ7) U10.G8(VSS3) U10.G9(VSSQ8) U10.J2(VSS4) U10.J8(VSS5) U10.M1(VSS6) U10.M9(VSS7) U10.P1(VSS8) U10.P9(VSS9) U10.T1(VSS10) U10.T3(A13) U10.T7(A14) U10.T9(VSS11) U11.A9(VSS0) U11.B1(VSSQ0) U11.B3(VSS1) U11.B9(VSSQ1) U11.D1(VSSQ2) U11.D8(VSSQ3) U11.E1(VSS2) U11.E2(VSSQ4) U11.E8(VSSQ5) U11.F9(VSSQ6) U11.G1(VSSQ7) U11.G8(VSS3) U11.G9(VSSQ8) U11.J2(VSS4) U11.J8(VSS5) U11.M1(VSS6) U11.M9(VSS7) U11.P1(VSS8) U11.P9(VSS9) U11.T1(VSS10) U11.T3(A13) U11.T7(A14) U11.T9(VSS11) U12.A9(VSS0) U12.B1(VSSQ0) U12.B3(VSS1) U12.B9(VSSQ1) U12.D1(VSSQ2) U12.D8(VSSQ3) U12.E1(VSS2) U12.E2(VSSQ4) U12.E8(VSSQ5) U12.F9(VSSQ6) U12.G1(VSSQ7) U12.G8(VSS3) U12.G9(VSSQ8) U12.J2(VSS4) U12.J8(VSS5) U12.M1(VSS6) U12.M9(VSS7) U12.P1(VSS8) U12.P9(VSS9) U12.T1(VSS10) U12.T3(A13) U12.T7(A14) U12.T9(VSS11) U26.4(I2C_LSB) U26.6(FDBK_N) U26.23(RSVD_GND) U26.25(EPAD) U33.2(GND) U35.3(GND1) U35.8(GND2) U36.3(GND1) U36.8(GND2) U37.7(GND1) U37.19(GND2) U37.30(GND3) U37.41(GND4) U37.49(PAD) U39.4(I2C_LSB) U39.6(FDBK_N) U39.23(RSVD_GND) U39.25(EPAD) U41.3(GND1) U41.8(GND2) U42.1(GND) U44.2(GND) U46.3(GND1) U46.8(GND2) U47.3(GND1) U47.8(GND2) U48.7(GND1) U48.19(GND2) U48.30(GND3) U48.41(GND4) U48.49(PAD) U49.3(GND1) U49.8(GND2) U55.1(GND) U59.25(VDD_SEL) U59.52(RESET) U59.55(GND) Y1.2(GND) Y2.2(GND) Y2.4(GND) Y3.2(GND) Y4.2(GND) Y4.4(GND) ; also on sheet 6 7 8 10 12 13 14 15 16 17
VCC_DDR3: C37.1 C38.1 C39.1 C40.1 C41.1 C42.1 C50.1 C51.1 C53.1 C55.1 C61.1 C62.1 C63.1 C77.1 C78.1 C79.1 C81.1 C82.1 C83.1 C84.1 C85.1 C96.1 C97.1 C98.1 C99.1 C100.1 C101.1 C103.1 C104.1 C105.1 C175.1 C219.1 C223.1 C239.1 C242.1 C255.1 U10.A1(VDDQ0) U10.A8(VDDQ1) U10.B2(VDD0) U10.C1(VDDQ2) U10.C9(VDDQ3) U10.D2(VDDQ4) U10.D9(VDD1) U10.E9(VDDQ5) U10.F1(VDDQ6) U10.G7(VDD2) U10.H2(VDDQ7) U10.H9(VDDQ8) U10.K2(VDD3) U10.K8(VDD4) U10.N1(VDD5) U10.N9(VDD6) U10.R1(VDD7) U10.R9(VDD8) U11.A1(VDDQ0) U11.A8(VDDQ1) U11.B2(VDD0) U11.C1(VDDQ2) U11.C9(VDDQ3) U11.D2(VDDQ4) U11.D9(VDD1) U11.E9(VDDQ5) U11.F1(VDDQ6) U11.G7(VDD2) U11.H2(VDDQ7) U11.H9(VDDQ8) U11.K2(VDD3) U11.K8(VDD4) U11.N1(VDD5) U11.N9(VDD6) U11.R1(VDD7) U11.R9(VDD8) U12.A1(VDDQ0) U12.A8(VDDQ1) U12.B2(VDD0) U12.C1(VDDQ2) U12.C9(VDDQ3) U12.D2(VDDQ4) U12.D9(VDD1) U12.E9(VDDQ5) U12.F1(VDDQ6) U12.G7(VDD2) U12.H2(VDDQ7) U12.H9(VDDQ8) U12.K2(VDD3) U12.K8(VDD4) U12.N1(VDD5) U12.N9(VDD6) U12.R1(VDD7) U12.R9(VDD8) ; also on sheet 10 14 15 16 17
VCC_IO3V0: R7.1 R11.1 R210.1 R233.1 R242.1 R273.1 R292.1 R300.1 U2.2(VREF1) U42.2(VREF1) U55.2(VREF1) ; also on sheet 6 7
VDD_PLL1: C248.1 C249.1 C256.1 C258.1 L6.1 R222.2 U39.11(VDDO3) U39.15(VDDO2) U39.16(VDDO1) U39.20(VDDO0)
VDD_PLL2: C159.1 C176.1 C180.1 C195.1 L5.1 R119.2 U26.11(VDDO3) U26.15(VDDO2) U26.16(VDDO1) U26.20(VDDO0)
25Mhz-1: R229.1 Y3.3(OUT)
25Mhz-2: R118.1 Y1.3(OUT)
5338_SCL1: U39.12(SCL) ; also on sheet 8
5338_SCL2: U26.12(SCL) ; also on sheet 8
5338_SDA1: U39.19(SDA) ; also on sheet 8
5338_SDA2: U26.19(SDA) ; also on sheet 8
A1_3: R464.1 R465.2 U37.27(TEST/A1)
A1_4: R477.1 R478.2 U48.27(TEST/A1)
CLK_USR: R154.1 U26.22(CLK0A)
CLKUSR: C196.2 R154.2 ; also on sheet 13
CONN_RCK+: C174.1 U26.14(CLK2A)
CONN_RCK-: C172.1 U26.13(CLK2B)
CONN_TX+0: P1.C34(GXBL1F_TX_CH1P_1F) ; also on sheet 12
CONN_TX+1: P1.E34(GXBL1F_TX_CH0P_1F) ; also on sheet 12
CONN_TX+2: P1.G34(GXBL1E_TX_CH5P_1E) ; also on sheet 12
CONN_TX+3: P1.J34(GXBL1E_TX_CH4P_1E) ; also on sheet 12
CONN_TX+4: P1.L34(GXBL1E_TX_CH3P_1E) ; also on sheet 12
CONN_TX+5: P1.N34(GXBL1E_TX_CH2P_1E) ; also on sheet 12
CONN_TX+6: P1.R34(GXBL1E_TX_CH1P_1E) ; also on sheet 12
CONN_TX+7: P1.U34(GXBL1E_TX_CH0P_1E) ; also on sheet 12
CONN_TX-0: P1.C33(GXBL1F_TX_CH1N_1F) ; also on sheet 12
CONN_TX-1: P1.E33(GXBL1F_TX_CH0N_1F) ; also on sheet 12
CONN_TX-2: P1.G33(GXBL1E_TX_CH5N_1E) ; also on sheet 12
CONN_TX-3: P1.J33(GXBL1E_TX_CH4N_1E) ; also on sheet 12
CONN_TX-4: P1.L33(GXBL1E_TX_CH3N_1E) ; also on sheet 12
CONN_TX-5: P1.N33(GXBL1E_TX_CH2N_1E) ; also on sheet 12
CONN_TX-6: P1.R33(GXBL1E_TX_CH1N_1E) ; also on sheet 12
CONN_TX-7: P1.U33(GXBL1E_TX_CH0N_1E) ; also on sheet 12
CONN_TX_RCK+: C174.2 P1.V28(REFCLK_GXBL1E_CHBP_1E)
CONN_TX_RCK-: C172.2 P1.V27(REFCLK_GXBL1E_CHBN_1E)
DDR3_A_A0: P1.H27(IO_2K_12_H27/LVDS2K_18P/DQ13) R35.2 U10.N3(A0) U11.N3(A0) U12.N3(A0)
DDR3_A_A1: P1.G27(IO_2K_13_G27/LVDS2K_18N/DQ13) R32.2 U10.P7(A1) U11.P7(A1) U12.P7(A1)
DDR3_A_A2: P1.G23(IO_2K_14_G23/LVDS2K_17P/DQ13) R36.2 U10.P3(A2) U11.P3(A2) U12.P3(A2)
DDR3_A_A3: P1.G22(IO_2K_15_G22/LVDS2K_17N/DQ13) R358.2 U10.N2(A3) U11.N2(A3) U12.N2(A3)
DDR3_A_A4: P1.H25(IO_2K_16_H25/LVDS2K_16P/DQS13) R365.2 U10.P8(A4) U11.P8(A4) U12.P8(A4)
DDR3_A_A5: P1.G25(IO_2K_17_G25/LVDS2K_16N/DQSN13) R357.2 U10.P2(A5) U11.P2(A5) U12.P2(A5)
DDR3_A_A6: P1.H24(IO_2K_18_H24/PLL_2K_CLKOUT0P,PLL_2K_CLKOUT0,PLL_2K_FB0/LVDS2K_15P/DQ12) R366.2 U10.R8(A6) U11.R8(A6) U12.R8(A6)
DDR3_A_A7: P1.H23(IO_2K_19_H23/PLL_2K_CLKOUT0N/LVDS2K_15N/DQ12) R356.2 U10.R2(A7) U11.R2(A7) U12.R2(A7)
DDR3_A_A8: P1.H22(IO_2K_20_H22/LVDS2K_14P/DQS12) R30.2 U10.T8(A8) U11.T8(A8) U12.T8(A8)
DDR3_A_A9: P1.J22(IO_2K_21_J22/LVDS2K_14N/DQSN12) R37.2 U10.R3(A9) U11.R3(A9) U12.R3(A9)
DDR3_A_A10: P1.G26(IO_2K_22_G26/CLK_2K_0P/LVDS2K_13P/DQ12) R363.2 U10.L7(A10/AP) U11.L7(A10/AP) U12.L7(A10/AP)
DDR3_A_A11: P1.F26(IO_2K_23_F26/CLK_2K_0N/LVDS2K_13N/DQ12) R31.2 U10.R7(A11) U11.R7(A11) U12.R7(A11)
DDR3_A_A12: P1.F24(IO_2K_27_F24/LVDS2K_11N/DQ11) R33.2 U10.N7(A12/BC#) U11.N7(A12/BC#) U12.N7(A12/BC#)
DDR3_A_BA0: P1.D26(IO_2K_33_D26/LVDS2K_8N/DQSN10) R359.2 U10.M2(BA0) U11.M2(BA0) U12.M2(BA0)
DDR3_A_BA1: P1.D25(IO_2K_34_D25/LVDS2K_7P/DQ10) R364.2 U10.N8(BA1) U11.N8(BA1) U12.N8(BA1)
DDR3_A_BA2: P1.C25(IO_2K_35_C25/LVDS2K_7N/DQ10) R34.2 U10.M3(BA2) U11.M3(BA2) U12.M3(BA2)
DDR3_A_CAS_N_0: P1.E26(IO_2K_32_E26/LVDS2K_8P/DQS10) R355.2 U10.K3(CAS#) U11.K3(CAS#) U12.K3(CAS#)
DDR3_A_CK_0: P1.L23(IO_2K_8_L23/LVDS2K_20P/DQS14) R380.2 U10.J7(CK) U11.J7(CK) U12.J7(CK)
DDR3_A_CK_N_0: P1.M23(IO_2K_9_M23/LVDS2K_20N/DQSN14) R380.1 U10.K7(CK#) U11.K7(CK#) U12.K7(CK#)
DDR3_A_CKE_0: P1.J27(IO_2K_6_J27/LVDS2K_21P/DQ14) R362.2 U10.K9(CKE) U11.K9(CKE) U12.K9(CKE)
DDR3_A_CS_N_0: P1.K24(IO_2K_2_K24/LVDS2K_23P/DQ15) R360.2 U10.L2(CS#) U11.L2(CS#) U12.L2(CS#)
DDR3_A_DM0: P1.AD25(IO_2J_47_AD25/LVDS2J_1N/DQ16) U11.E7(LDM)
DDR3_A_DM1: P1.AM27(IO_2J_35_AM27/LVDS2J_7N/DQ18) U11.D3(UDM)
DDR3_A_DM2: P1.AP24(IO_2J_23_AP24/CLK_2J_0N/LVDS2J_13N/DQ20) U12.E7(LDM)
DDR3_A_DM3: P1.AE23(IO_2J_11_AE23/LVDS2J_19N/DQ22) U12.D3(UDM)
DDR3_A_DM4: P1.C23(IO_2K_47_C23/LVDS2K_1N/DQ8) U10.E7(LDM)
DDR3_A_DQ0: P1.AJ27(IO_2J_44_AJ27/LVDS2J_2P/DQS16) U11.E3(DQ0)
DDR3_A_DQ1: P1.AH27(IO_2J_45_AH27/LVDS2J_2N/DQSN16) U11.F7(DQ1)
DDR3_A_DQ2: P1.AJ26(IO_2J_42_AJ26/LVDS2J_3P/DQ16) U11.F2(DQ2)
DDR3_A_DQ3: P1.AD24(IO_2J_37_AD24/LVDS2J_6N/DQ17) U11.F8(DQ3)
DDR3_A_DQ4: P1.AJ25(IO_2J_38_AJ25/LVDS2J_5P/DQ17) U11.H3(DQ4)
DDR3_A_DQ5: P1.AE24(IO_2J_46_AE24/LVDS2J_1P/DQ16) U11.H8(DQ5)
DDR3_A_DQ6: P1.AH25(IO_2J_39_AH25/LVDS2J_5N/DQ17) U11.G2(DQ6)
DDR3_A_DQ7: P1.AH26(IO_2J_43_AH26/LVDS2J_3N/DQ16) U11.H7(DQ7)
DDR3_A_DQ8: P1.AN27(IO_2J_34_AN27/LVDS2J_7P/DQ18) U11.D7(DQ8)
DDR3_A_DQ9: P1.AP27(IO_2J_33_AP27/LVDS2J_8N/DQSN18) U11.C3(DQ9)
DDR3_A_DQ10: P1.AK26(IO_2J_31_AK26/LVDS2J_9N/DQ18) U11.C8(DQ10)
DDR3_A_DQ11: P1.AN25(IO_2J_27_AN25/LVDS2J_11N/DQ19) U11.C2(DQ11)
DDR3_A_DQ12: P1.AL26(IO_2J_25_AL26/CLK_2J_1N/LVDS2J_12N/DQ19) U11.A7(DQ12)
DDR3_A_DQ13: P1.AP25(IO_2J_26_AP25/RZQ_2J/LVDS2J_11P/DQ19) U11.A2(DQ13)
DDR3_A_DQ14: P1.AK27(IO_2J_30_AK27/LVDS2J_9P/DQ18) U11.B8(DQ14)
DDR3_A_DQ15: P1.AP26(IO_2J_32_AP26/LVDS2J_8P/DQS18) U11.A3(DQ15)
DDR3_A_DQ16: P1.AN23(IO_2J_15_AN23/LVDS2J_17N/DQ21) U12.E3(DQ0)
DDR3_A_DQ17: P1.AM23(IO_2J_14_AM23/LVDS2J_17P/DQ21) U12.F7(DQ1)
DDR3_A_DQ18: P1.AP20(IO_2J_13_AP20/LVDS2J_18N/DQ21) U12.F2(DQ2)
DDR3_A_DQ19: P1.AL24(IO_2J_20_AL24/LVDS2J_14P/DQS20) U12.F8(DQ3)
DDR3_A_DQ20: P1.AP21(IO_2J_18_AP21/PLL_2J_CLKOUT0P,PLL_2J_CLKOUT0,PLL_2J_FB0/LVDS2J_15P/DQ20) U12.H3(DQ4)
DDR3_A_DQ21: P1.AL25(IO_2J_21_AL25/LVDS2J_14N/DQSN20) U12.H8(DQ5)
DDR3_A_DQ22: P1.AP22(IO_2J_19_AP22/PLL_2J_CLKOUT0N/LVDS2J_15N/DQ20) U12.G2(DQ6)
DDR3_A_DQ23: P1.AN24(IO_2J_22_AN24/CLK_2J_0P/LVDS2J_13P/DQ20) U12.H7(DQ7)
DDR3_A_DQ24: P1.AL23(IO_2J_2_AL23/LVDS2J_23P/DQ23) U12.D7(DQ8)
DDR3_A_DQ25: P1.AG23(IO_2J_9_AG23/LVDS2J_20N/DQSN22) U12.C3(DQ9)
DDR3_A_DQ26: P1.AK24(IO_2J_7_AK24/LVDS2J_21N/DQ22) U12.C8(DQ10)
DDR3_A_DQ27: P1.AK23(IO_2J_3_AK23/LVDS2J_23N/DQ23) U12.C2(DQ11)
DDR3_A_DQ28: P1.AF24(IO_2J_10_AF24/LVDS2J_19P/DQ22) U12.A7(DQ12)
DDR3_A_DQ29: P1.AF23(IO_2J_8_AF23/LVDS2J_20P/DQS22) U12.A2(DQ13)
DDR3_A_DQ30: P1.AJ24(IO_2J_6_AJ24/LVDS2J_21P/DQ22) U12.B8(DQ14)
DDR3_A_DQ31: P1.AK22(IO_2J_1_AK22/LVDS2J_24N/DQ23) U12.A3(DQ15)
DDR3_A_DQ32: P1.B27(IO_2K_43_B27/LVDS2K_3N/DQ8) U10.E3(DQ0)
DDR3_A_DQ33: P1.A24(IO_2K_37_A24/LVDS2K_6N/DQ9) U10.F7(DQ1)
DDR3_A_DQ34: P1.A26(IO_2K_45_A26/LVDS2K_2N/DQSN8) U10.F2(DQ2)
DDR3_A_DQ35: P1.B23(IO_2K_46_B23/LVDS2K_1P/DQ8) U10.F8(DQ3)
DDR3_A_DQ36: P1.C27(IO_2K_42_C27/LVDS2K_3P/DQ8) U10.H3(DQ4)
DDR3_A_DQ37: P1.A25(IO_2K_39_A25/LVDS2K_5N/DQ9) U10.H8(DQ5)
DDR3_A_DQ38: P1.B26(IO_2K_44_B26/LVDS2K_2P/DQS8) U10.G2(DQ6)
DDR3_A_DQ39: P1.B25(IO_2K_38_B25/LVDS2K_5P/DQ9) U10.H7(DQ7)
DDR3_A_DQS0N: P1.AF25(IO_2J_41_AF25/LVDS2J_4N/DQSN17) U11.G3(LDQS#)
DDR3_A_DQS0P: P1.AG25(IO_2J_40_AG25/LVDS2J_4P/DQS17) U11.F3(LDQS)
DDR3_A_DQS1N: P1.AM26(IO_2J_29_AM26/PLL_2J_CLKOUT1N/LVDS2J_10N/DQSN19) U11.B7(UDQS#)
DDR3_A_DQS1P: P1.AM25(IO_2J_28_AM25/PLL_2J_CLKOUT1P,PLL_2J_CLKOUT1,PLL_2J_FB1/LVDS2J_10P/DQS19) U11.C7(UDQS)
DDR3_A_DQS2N: P1.AN22(IO_2J_17_AN22/LVDS2J_16N/DQSN21) U12.G3(LDQS#)
DDR3_A_DQS2P: P1.AM22(IO_2J_16_AM22/LVDS2J_16P/DQS21) U12.F3(LDQS)
DDR3_A_DQS3N: P1.AH24(IO_2J_5_AH24/LVDS2J_22N/DQSN23) U12.B7(UDQS#)
DDR3_A_DQS3P: P1.AH23(IO_2J_4_AH23/LVDS2J_22P/DQS23) U12.C7(UDQS)
DDR3_A_DQS4N: P1.D24(IO_2K_41_D24/LVDS2K_4N/DQSN9) U10.G3(LDQS#)
DDR3_A_DQS4P: P1.C24(IO_2K_40_C24/LVDS2K_4P/DQS9) U10.F3(LDQS)
DDR3_A_ODT_0: P1.K25(IO_2K_4_K25/LVDS2K_22P/DQS15) R354.2 U10.K1(ODT) U11.K1(ODT) U12.K1(ODT)
DDR3_A_RAS_N_0: P1.F23(IO_2K_31_F23/LVDS2K_9N/DQ10) R353.2 U10.J3(RAS#) U11.J3(RAS#) U12.J3(RAS#)
DDR3_A_RST_N_0: C32.1 P1.L24(IO_2K_1_L24/LVDS2K_24N/DQ15) U10.T2(RESET#) U11.T2(RESET#) U12.T2(RESET#)
DDR3_A_WE_N_0: P1.M24(IO_2K_0_M24/LVDS2K_24P/DQ15) R361.2 U10.L3(WE#) U11.L3(WE#) U12.L3(WE#)
DDR3A_N: C247.2 P1.E24(IO_2K_25_E24/CLK_2K_1N/LVDS2K_12N/DQ11)
DDR3A_P: C246.2 P1.E23(IO_2K_24_E23/CLK_2K_1P/LVDS2K_12P/DQ11)
DDR3B_N: C262.2 ; also on sheet 15
DDR3B_P: C259.2 ; also on sheet 15
DDR3C_N: C251.2 ; also on sheet 14
DDR3C_P: C250.2 ; also on sheet 14
DEM_D0: R341.1 R342.1 U59.53(DEM_D0)
DEM_D1: R338.1 R339.1 U59.54(DEM_D1)
ENSMB: R350.1 R351.1 U59.48(ENSMB)
EQ_D0: R337.1 R340.1 U59.20(EQ_D0)
EQ_D1: R335.1 R336.1 U59.19(EQ_D1)
EQ_S0: R371.1 R372.1 U59.46(EQ_S0)
EQ_S1: R368.1 R369.1 U59.47(EQ_S1)
EQ_SEL/A0_3: R200.2 R201.1 U37.21(EQ_SEL/A0)
EQ_SEL/A0_4: R262.2 R263.1 U48.21(EQ_SEL/A0)
HD_SCL3: R234.2 R241.1 R243.2 U42.6(SCL2)
HD_SCL4: R294.2 R299.1 R301.2 U55.6(SCL2)
HD_SDA3: R235.2 R236.1 R244.2 U42.5(SDA2)
HD_SDA4: R295.2 R296.1 R302.2 U55.5(SDA2)
HDMI20_RX_RCK+: C428.1 U59.31(S_OUTA1p)
HDMI20_RX_RCK-: C426.1 U59.30(S_OUTA1n)
HDMI21_RX+: C264.1 U39.22(CLK0A)
HDMI21_RX-: C261.1 U39.21(CLK0B)
HDMI21_RX_RCK+: C264.2 P1.AF28(REFCLK_GXBL1C_CHBP_1C)
HDMI21_RX_RCK-: C261.2 P1.AF27(REFCLK_GXBL1C_CHBN_1C)
HDMI_3_TCX+: J10.10(CLK+) R214.2 U36.4(IO3) U36.7(NC3) U37.26(OUT_CLKP)
HDMI_3_TCX-: J10.12(CLK-) R213.2 U36.5(IO4) U36.6(NC4) U37.25(OUT_CLKN)
HDMI_3_TX0+: J10.7(DAT0+) R217.2 U36.1(IO1) U36.10(NC1) U37.29(OUT_D0P)
HDMI_3_TX0-: J10.9(DAT0-) R215.2 U36.2(IO2) U36.9(NC2) U37.28(OUT_D0N)
HDMI_3_TX1+: J10.4(DAT1+) R219.2 U37.32(OUT_D1P) U41.4(IO3) U41.7(NC3)
HDMI_3_TX1-: J10.6(DAT1-) R218.2 U37.31(OUT_D1N) U41.5(IO4) U41.6(NC4)
HDMI_3_TX2+: J10.1(DAT2+) R223.2 U37.35(OUT_D2P) U41.1(IO1) U41.10(NC1)
HDMI_3_TX2-: J10.3(DAT2-) R220.2 U37.34(OUT_D2N) U41.2(IO2) U41.9(NC2)
HDMI_4_TCX+: J14.10(CLK+) R276.2 U47.4(IO3) U47.7(NC3) U48.26(OUT_CLKP)
HDMI_4_TCX-: J14.12(CLK-) R275.2 U47.5(IO4) U47.6(NC4) U48.25(OUT_CLKN)
HDMI_4_TX0+: J14.7(DAT0+) R278.2 U47.1(IO1) U47.10(NC1) U48.29(OUT_D0P)
HDMI_4_TX0-: J14.9(DAT0-) R277.2 U47.2(IO2) U47.9(NC2) U48.28(OUT_D0N)
HDMI_4_TX1+: J14.4(DAT1+) R280.2 U48.32(OUT_D1P) U49.4(IO3) U49.7(NC3)
HDMI_4_TX1-: J14.6(DAT1-) R279.2 U48.31(OUT_D1N) U49.5(IO4) U49.6(NC4)
HDMI_4_TX2+: J14.1(DAT2+) R282.2 U48.35(OUT_D2P) U49.1(IO1) U49.10(NC1)
HDMI_4_TX2-: J14.3(DAT2-) R281.2 U48.34(OUT_D2N) U49.2(IO2) U49.9(NC2)
HDMI_HPD_21: HDMI1.19(HPLG) Q2.3(D) R8.2 U3.4(IO3) U3.7(NC3)
HDMI_HPD_IN3: Q5.3(D) R210.2 R466.2 R467.2
HDMI_HPD_IN4: Q6.3(D) R273.2 R479.2 R480.2
HDMI_RX0n: C398.1 HDMI1.3(DAT2-) R25.2 U7.2(IO2) U7.9(NC2)
HDMI_RX0p: C399.1 HDMI1.1(DAT2+) R39.2 U7.1(IO1) U7.10(NC1)
HDMI_RX1n: C400.1 HDMI1.6(DAT1-) R21.2 U7.5(IO4) U7.6(NC4)
HDMI_RX1p: C401.1 HDMI1.4(DAT1+) R24.2 U7.4(IO3) U7.7(NC3)
HDMI_RX2n: C392.1 HDMI1.9(DAT0-) R18.2 U4.2(IO2) U4.9(NC2)
HDMI_RX2p: C393.1 HDMI1.7(DAT0+) R20.2 U4.1(IO1) U4.10(NC1)
HDMI_RX3n: C390.1 HDMI1.12(CLK-) R16.2 U4.5(IO4) U4.6(NC4)
HDMI_RX3p: C391.1 HDMI1.10(CLK+) R17.2 U4.4(IO3) U4.7(NC3)
HDMI_RXC0n: C398.2 U59.39(S_INA1n)
HDMI_RXC0p: C399.2 U59.40(S_INA1p)
HDMI_RXC1n: C400.2 U59.44(S_INA0n)
HDMI_RXC1p: C401.2 U59.45(S_INA0p)
HDMI_RXC2n: C392.2 U59.11(D_IN0n)
HDMI_RXC2p: C393.2 U59.10(D_IN0p)
HDMI_RXC3n: C390.2 U59.16(D_IN1n)
HDMI_RXC3p: C391.2 U59.15(D_IN1p)
HDMI_SCL_3: J10.15(SCL) R230.1 R239.1 R243.1 U35.1(IO1) U35.10(NC1)
HDMI_SCL_4: J14.15(SCL) R288.1 R297.1 R301.1 U46.1(IO1) U46.10(NC1)
HDMI_SCL_21: HDMI1.15(SCL) U2.6(SCL2) U3.1(IO1) U3.10(NC1)
HDMI_SDA_3: J10.16(SDA) R231.1 R240.1 R244.1 U35.2(IO2) U35.9(NC2)
HDMI_SDA_4: J14.16(SDA) R289.1 R298.1 R302.1 U46.2(IO2) U46.9(NC2)
HDMI_SDA_21: HDMI1.16(SDA) U2.5(SDA2) U3.2(IO2) U3.9(NC2)
HM20_RX_RCK+: C428.2 P1.AD28(REFCLK_GXBL1C_CHTP_1C)
HM20_RX_RCK-: C426.2 P1.AD27(REFCLK_GXBL1C_CHTN_1C)
HM20_TX+: C160.1 U26.10(CLK3A)
HM20_TX-: C161.1 U26.9(CLK3B)
HM20_TX_RCX+: C160.2 P1.AB28(REFCLK_GXBL1D_CHBP_1D)
HM20_TX_RCX-: C161.2 P1.AB27(REFCLK_GXBL1D_CHBN_1D)
HM21_RX0+: C664.1 U59.29(S_OUTB1p)
HM21_RX0-: C663.1 U59.28(S_OUTB1n)
HM21_RX1+: C662.1 U59.35(S_OUTA0p)
HM21_RX1-: C661.1 U59.34(S_OUTA0n)
HM21_RX2+: C666.1 U59.7(D_OUT1p)
HM21_RX2-: C665.1 U59.8(D_OUT1n)
HM21_RX3+: C668.1 U59.3(D_OUT0p)
HM21_RX3-: C667.1 U59.4(D_OUT0n)
HM21_SCL: R344.1 R345.1 U59.50(DEM_S1) ; also on sheet 13
HM21_SDA: R347.1 R348.1 U59.49(DEM_S0) ; also on sheet 13
HM21RX0+: C664.2 P1.AG30(GXBL1C_RX_CH2P,GXBL1C_REFCLK2P_1C)
HM21RX0-: C663.2 P1.AG29(GXBL1C_RX_CH2N,GXBL1C_REFCLK2N_1C)
HM21RX1+: C662.2 P1.AF32(GXBL1C_RX_CH3P,GXBL1C_REFCLK3P_1C)
HM21RX1-: C661.2 P1.AF31(GXBL1C_RX_CH3N,GXBL1C_REFCLK3N_1C)
HM21RX2+: C666.2 P1.AJ30(GXBL1C_RX_CH1P,GXBL1C_REFCLK1P_1C)
HM21RX2-: C665.2 P1.AJ29(GXBL1C_RX_CH1N,GXBL1C_REFCLK1N_1C)
HM21RX3+: C668.2 P1.AL30(GXBL1C_RX_CH0P,GXBL1C_REFCLK0P_1C)
HM21RX3-: C667.2 P1.AL29(GXBL1C_RX_CH0N,GXBL1C_REFCLK0N_1C)
HM_1_TCX+: P1.AH32(GXBL1C_TX_CH3P_1C) ; also on sheet 7
HM_1_TCX-: P1.AH31(GXBL1C_TX_CH3N_1C) ; also on sheet 7
HM_1_TX0+: P1.AP32(GXBL1C_TX_CH0P_1C) ; also on sheet 7
HM_1_TX0-: P1.AP31(GXBL1C_TX_CH0N_1C) ; also on sheet 7
HM_1_TX1+: P1.AM32(GXBL1C_TX_CH1P_1C) ; also on sheet 7
HM_1_TX1-: P1.AM31(GXBL1C_TX_CH1N_1C) ; also on sheet 7
HM_1_TX2+: P1.AK32(GXBL1C_TX_CH2P_1C) ; also on sheet 7
HM_1_TX2-: P1.AK31(GXBL1C_TX_CH2N_1C) ; also on sheet 7
HM_2_TCX+: P1.AG34(GXBL1D_TX_CH1P_1D) ; also on sheet 6
HM_2_TCX-: P1.AG33(GXBL1D_TX_CH1N_1D) ; also on sheet 6
HM_2_TX0+: P1.AN34(GXBL1C_TX_CH4P_1C) ; also on sheet 6
HM_2_TX0-: P1.AN33(GXBL1C_TX_CH4N_1C) ; also on sheet 6
HM_2_TX1+: P1.AL34(GXBL1C_TX_CH5P_1C) ; also on sheet 6
HM_2_TX1-: P1.AL33(GXBL1C_TX_CH5N_1C) ; also on sheet 6
HM_2_TX2+: P1.AJ34(GXBL1D_TX_CH0P_1D) ; also on sheet 6
HM_2_TX2-: P1.AJ33(GXBL1D_TX_CH0N_1D) ; also on sheet 6
HM_3_TCX+: C252.1 P1.W34(GXBL1D_TX_CH5P_1D)
HM_3_TCX-: C245.1 P1.W33(GXBL1D_TX_CH5N_1D)
HM_3_TX0+: C257.1 P1.AE34(GXBL1D_TX_CH2P_1D)
HM_3_TX0-: C254.1 P1.AE33(GXBL1D_TX_CH2N_1D)
HM_3_TX1+: C263.1 P1.AC34(GXBL1D_TX_CH3P_1D)
HM_3_TX1-: C260.1 P1.AC33(GXBL1D_TX_CH3N_1D)
HM_3_TX2+: C269.1 P1.AA34(GXBL1D_TX_CH4P_1D)
HM_3_TX2-: C266.1 P1.AA33(GXBL1D_TX_CH4N_1D)
HM_4_TCX+: C296.1 P1.B32(GXBL1F_TX_CH5P_1F)
HM_4_TCX-: C295.1 P1.B31(GXBL1F_TX_CH5N_1F)
HM_4_TX0+: C301.1 P1.H32(GXBL1F_TX_CH2P_1F)
HM_4_TX0-: C300.1 P1.H31(GXBL1F_TX_CH2N_1F)
HM_4_TX1+: C331.1 P1.F32(GXBL1F_TX_CH3P_1F)
HM_4_TX1-: C302.1 P1.F31(GXBL1F_TX_CH3N_1F)
HM_4_TX2+: C333.1 P1.D32(GXBL1F_TX_CH4P_1F)
HM_4_TX2-: C332.1 P1.D31(GXBL1F_TX_CH4N_1F)
HM_SCL_3: J9.2 R209.2 ; also on sheet 13
HM_SCL_4: J12.2 R271.2 ; also on sheet 13
HM_SDA_3: J9.1 R207.2 ; also on sheet 13
HM_SDA_4: J12.1 R269.2 ; also on sheet 13
HM_TX_HPD3: R467.1 R468.1 ; also on sheet 13
HM_TX_HPD4: R480.1 R481.1 ; also on sheet 13
HM_TX_SCL3: R242.2 U42.3(SCL1) ; also on sheet 13
HM_TX_SCL4: R300.2 U55.3(SCL1) ; also on sheet 13
HM_TX_SCL21: U2.3(SCL1) ; also on sheet 13
HM_TX_SDA3: R233.2 U42.4(SDA1) ; also on sheet 13
HM_TX_SDA4: R292.2 U55.4(SDA1) ; also on sheet 13
HM_TX_SDA21: U2.4(SDA1) ; also on sheet 13
HPD_IN3: J10.19(HPLG) Q5.1(G) R211.2 R469.2 U35.5(IO4) U35.6(NC4)
HPD_IN4: J14.19(HPLG) Q6.1(G) R274.2 R482.2 U46.5(IO4) U46.6(NC4)
HPD_SNK_3: R466.1 R469.1 U37.33(HPD_SNK)
HPD_SNK_4: R479.1 R482.1 U48.33(HPD_SNK)
HPD_SRC_3: R468.2 U37.4(HPD_SRC)
HPD_SRC_4: R481.2 U48.4(HPD_SRC)
I2C_EN/PIN_3: R462.2 R463.1 U37.10(I2C_EN/PIN)
I2C_EN/PIN_4: R475.2 R476.1 U48.10(I2C_EN/PIN)
MODE: R343.1 R346.1 U59.21(MODE)
PRE_SEL_3: R202.1 R203.2 U37.20(PRE_SEL)
PRE_SEL_4: R264.1 R265.2 U48.20(PRE_SEL)
R0PWR5V: HDMI1.18(+5V) R12.1 U3.5(IO4) U3.6(NC4)
RC_F_N: C184.1 U26.17(CLK1B)
RC_F_P: C186.1 U26.18(CLK1A)
REFCLK_F_N: C184.2 P1.P27(REFCLK_GXBL1F_CHBN_1F)
REFCLK_F_P: C186.2 P1.P28(REFCLK_GXBL1F_CHBP_1F)
RX_5V_N: Q1.3(D) R7.2 ; also on sheet 13
RX_HPD_N: Q2.1(G) R11.2 ; also on sheet 13
SCL_CTL_3: R208.2 R209.1 U37.15(SCL_CTL)
SCL_CTL_4: R270.2 R271.1 U48.15(SCL_CTL)
SCL_SNK_3: R230.2 U37.38(SCL_SNK)
SCL_SNK_4: R288.2 U48.38(SCL_SNK)
SCL_SRC_3: R226.1 R234.1 U37.46(SCL_SRC)
SCL_SRC_4: R286.1 R294.1 U48.46(SCL_SRC)
SDA_CTL_3: R206.2 R207.1 U37.16(SDA_CTL)
SDA_CTL_4: R268.2 R269.1 U48.16(SDA_CTL)
SDA_SNK_3: R231.2 U37.39(SDA_SNK)
SDA_SNK_4: R289.2 U48.39(SDA_SNK)
SDA_SRC_3: R227.1 R235.1 U37.47(SDA_SRC)
SDA_SRC_4: R287.1 R295.1 U48.47(SDA_SRC)
SEL0: R352.1 R367.1 U59.23(SEL0)
SEL1: R370.1 R373.1 U59.26(SEL1)
si_DDR3A_N: C247.1 U39.17(CLK1B)
si_DDR3A_P: C246.1 U39.18(CLK1A)
si_DDR3B_N: C262.1 U39.9(CLK3B)
si_DDR3B_P: C259.1 U39.10(CLK3A)
si_DDR3C_N: C251.1 U39.13(CLK2B)
si_DDR3C_P: C250.1 U39.14(CLK2A)
SIG_EN_3: R204.1 R205.2 U37.17(SIG_EN)
SIG_EN_4: R266.1 R267.2 U48.17(SIG_EN)
SWAP/POL_3: R470.1 R471.2 U37.1(SWAP/POL)
SWAP/POL_4: R484.1 R485.2 U48.1(SWAP/POL)
TX_TERM_3: R472.1 R473.2 U37.36(TX_TERM_CTL)
TX_TERM_4: R486.1 R487.2 U48.36(TX_TERM_CTL)
VREF_DDR3_A: C11.1 C64.1 C65.1 C66.1 C445.1 C579.1 P1.AC23(VREFB2JN0_2J) P1.M22(VREFB2KN0_2K) U10.H1(VREFDQ) U10.M8(VREFCA) U11.H1(VREFDQ) U11.M8(VREFCA) U12.H1(VREFDQ) U12.M8(VREFCA) ; also on sheet 10
VTT_DDR3_A: C394.1 C395.1 C396.1 C397.1 R30.1 R31.1 R32.1 R33.1 R34.1 R35.1 R36.1 R37.1 R353.1 R354.1 R355.1 R356.1 R357.1 R358.1 R359.1 R360.1 R361.1 R362.1 R363.1 R364.1 R365.1 R366.1 ; also on sheet 10
XTL25N1: C271.2 U39.2(CLKIN_N) Y4.1(XTALI)
XTL25N2: C182.2 U26.2(CLKIN_N) Y2.1(XTALI)
XTL25P1: C270.2 U39.1(CLKIN_P) Y4.3(XTALO)
XTL25P2: C189.2 U26.1(CLKIN_P) Y2.3(XTALO)
N22047900: P1.M27(REFCLK_GXBL1F_CHTN_1F) P1.M28(REFCLK_GXBL1F_CHTP_1F) R443.2
N22048190: P1.AP29(RREF_BL) R396.2
N22048192: P1.A29(RREF_TL) R461.2
N22048413: L20.1 P1.A14(ADCGND)
N22049180: R228.2 R229.2 U39.3(CLKIN)
N22049282: R222.1 U39.8(INTR)
N22049606: R246.2 Y3.1(EN)
N22053758: R50.2 U12.L8(ZQ)
N22054851: P1.F25(IO_2K_26_F25/RZQ_2K/LVDS2K_11P/DQ11) R457.1
N22055520: R48.2 U10.L8(ZQ)
N22056050: R49.2 U11.L8(ZQ)
N22341695: C263.2 U37.5(IN_D1P)
N22341697: C260.2 U37.6(IN_D1N)
N22341699: C269.2 U37.2(IN_D2P)
N22341701: C266.2 U37.3(IN_D2N)
N22341875: C274.1 J10.MTG1 J10.MTG2 J10.MTG3 J10.MTG4 R193.2
N22341965: C282.2 R248.1 U42.7(VREF2) U42.8(EN)
N22341967: C257.2 U37.8(IN_D0P)
N22342656: C254.2 U37.9(IN_D0N)
N22342658: C252.2 U37.11(IN_CLKP)
N22342660: C245.2 U37.12(IN_CLKN)
N22342772: R199.2 U37.22(VSADJ)
N22342834: R232.1 U37.45(SPDIF_IN)
N22342850: C272.1 U37.42(OE)
N22343231: J10.18(+5V) R196.1
N22343268: R194.2 U33.3(OCB)
N22343279: R176.1 R177.1 U33.4(EN)
N22346984: C331.2 U48.5(IN_D1P)
N22347001: C302.2 U48.6(IN_D1N)
N22347003: C333.2 U48.2(IN_D2P)
N22347005: C332.2 U48.3(IN_D2N)
N22347179: C338.1 J14.MTG1 J14.MTG2 J14.MTG3 J14.MTG4 R253.2
N22347257: C364.2 R303.1 U55.7(VREF2) U55.8(EN)
N22347259: C301.2 U48.8(IN_D0P)
N22347960: C300.2 U48.9(IN_D0N)
N22347962: C296.2 U48.11(IN_CLKP)
N22347964: C295.2 U48.12(IN_CLKN)
N22348076: R261.2 U48.22(VSADJ)
N22348138: R290.1 U48.45(SPDIF_IN)
N22348154: C335.1 U48.42(OE)
N22348531: J14.18(+5V) R258.1
N22348572: R257.2 U44.3(OCB)
N22348576: R251.1 R252.1 U44.4(EN)
N22353387: R118.2 R134.2 U26.3(CLKIN)
N22353420: R119.1 U26.8(INTR)
N22353722: R133.2 Y1.1(EN)
N22359824: P1.T27(REFCLK_GXBL1E_CHTN_1E) P1.T28(REFCLK_GXBL1E_CHTP_1E) R434.2
N22360101: P1.Y27(REFCLK_GXBL1D_CHTN_1D) P1.Y28(REFCLK_GXBL1D_CHTP_1D) R427.2
N22376675: C43.1 HDMI1.MTG1 HDMI1.MTG2 HDMI1.MTG3 HDMI1.MTG4 R10.2
N22380384: C4.2 R13.1 U2.7(VREF2) U2.8(EN)
N22381237: R349.1 U59.22(INPUT_EN)
N22381770: R27.2 U59.43(S_INB0p)
N22381784: R26.2 U59.42(S_INB0n)
N22381826: R29.2 U59.38(S_INB1p)
N22381836: R28.2 U59.37(S_INB1n)
N22382472: C20.1 U59.41(VDD)
N22382559: C21.1 U59.36(VDD)
N22383207: C5.1 U59.9(VDD)
N22383495: C6.1 U59.14(VDD)
N22383981: C12.1 U59.51(VDD)
N22398516: Q1.1(G) R6.2 R9.1 R12.2

Not connected (* = marked no-connect by the designer): HDMI1 13(CEC)* 14(NC)*; J10 13(CEC) 14(NC)*; J14 13(CEC) 14(NC)*; P1 A2(NC) A3(NC) A4(NC) A5(NC) A6(NC) A8(NC) A9(NC) A10(NC) A11(NC) A15(NC) A16(NC) A23(IO_2K_36_A23/LVDS2K_6P/DQ9) AC13(DNU) AC14(DNU) AC15(DNU) AC20(NC) AC22(NC) AC24(IO_2J_36_AC24/LVDS2J_6P/DQ17) AD20(NC) AD22(NC) AE20(NC) AE21(NC) AE22(NC) AF20(NC) AF21(NC) AF22(NC) AG20(NC) AG21(NC) AG22(NC) AH20(NC) AH22(NC) AJ19(NC) AJ20(NC) AJ21(NC) AJ22(IO_2J_0_AJ22/LVDS2J_24P/DQ23) AK19(NC) AK20(NC) AK21(NC) AL19(NC) AL20(NC) AL21(NC) AL27(IO_2J_24_AL27/CLK_2J_1P/LVDS2J_12P/DQ19) AM20(NC) AM21(NC) AN1(NC) AN2(NC) AN3(NC) AN19(NC) AN20(IO_2J_12_AN20/LVDS2J_18P/DQ21) AN28(DNU) AN29(DNU) AP2(NC) AP3(NC) AP19(NC) B1(NC) B3(NC) B5(NC) B6(NC) B7(NC) B8(NC) B10(NC) B11(NC) B12(NC) B15(NC) B16(NC) B17(NC) C2(NC) C3(NC) C4(NC) C5(NC) C7(NC) C8(NC) C9(NC) C10(NC) C12(NC) C13(NC) C15(NC) C17(NC) D1(NC) D2(NC) D4(NC) D5(NC) D6(NC) D7(NC) D9(NC) D10(NC) D11(NC) D12(NC) D15(NC) D16(NC) D27(IO_2K_29_D27/PLL_2K_CLKOUT1N/LVDS2K_10N/DQSN11) E1(NC) E2(NC) E3(NC) E4(NC) E6(NC) E7(NC) E8(NC) E9(NC) E11(NC) E12(NC) E13(NC) E16(NC) E22(IO_2K_30_E22/LVDS2K_9P/DQ10) E27(IO_2K_28_E27/PLL_2K_CLKOUT1P,PLL_2K_CLKOUT1,PLL_2K_FB1/LVDS2K_10P/DQS11) F1(NC) F3(NC) F4(NC) F5(NC) F6(NC) F8(NC) F9(NC) F10(NC) F11(NC) F12(NC) F13(NC) F15(NC) F16(NC) G1(NC) G2(NC) G3(NC) G5(NC) G6(NC) G7(NC) G8(NC) G10(NC) G11(NC) G12(NC) G13(NC) G15(NC) G16(NC) H2(NC) H3(NC) H4(NC) H5(NC) H7(NC) H8(NC) H9(NC) H10(NC) H11(NC) H12(NC) H13(NC) H15(NC) J6(NC) J7(NC) J9(NC) J10(NC) J11(NC) J12(NC) J13(NC) J24(IO_2K_3_J24/LVDS2K_23N/DQ15) J25(IO_2K_5_J25/LVDS2K_22N/DQSN15) J26(IO_2K_7_J26/LVDS2K_21N/DQ14) K8(NC) K9(NC) K10(NC) K11(NC) K12(NC) K13(NC) K14(NC) K22(IO_2K_11_K22/LVDS2K_19N/DQ14) K23(IO_2K_10_K23/LVDS2K_19P/DQ14) L9(NC) L10(NC) L11(NC) L13(NC) L14(NC) M9(NC) M10(NC) M11(NC) M12(NC) M13(NC) N10(NC) N11(NC) P10(NC) T14(NC) T15(NC); U10 B7(UDQS#) C7(UDQS) D3(UDM) J1(NC0)* J9(NC1)* L1(NC2)* L9(NC3)* M7(NC4)*; U11 J1(NC0)* J9(NC1)* L1(NC2)* L9(NC3)* M7(NC4)*; U12 J1(NC0)* J9(NC1)* L1(NC2)* L9(NC3)* M7(NC4)*; U26 5(FDBK_P)* 21(CLK0B); U35 4(IO3) 7(NC3); U37 18(NC1) 40(NC2) 44(ARC_OUT)*; U39 5(FDBK_P)*; U46 4(IO3) 7(NC3); U48 18(NC1) 40(NC2) 44(ARC_OUT)*; U59 1(NC0) 2(NC1) 5(NC2) 6(NC3) 12(NC4) 13(NC5) 17(NC6) 18(NC7) 27(ALL_DONE_N) 32(S_OUTB0n) 33(S_OUTB0p)

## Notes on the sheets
sheet 1
- 当ENSMB=1时，
  EQ_S0\EQ_S1\DEM_D0\DEM_D1为地址管脚。
  DEM_S0\DEM_S1为I2C配置管脚。
sheet 2
- HDMI OUT4
- 差分信号的输入端是否加电容
  输出端是否加电感
- 电源去耦电容
- TMDS181配置管脚
- 5V输出限流
- 5V电源输出限流+防倒灌，limit（A）=6800/Rocb
- TMDS181芯片配置：I2C控制模式
- DDC输出选择
- HPD接入选择
- HPD信号经过TMDS181芯片转接，R392上件，R393 NC
  HPD信号直接由FPGA控制，R393上件，R392 NC
- DDCI2C 可选择接入TMDS181的SRC_I2C（默认）
  或者 直接接到PCA9306DC1A的I2C输入接口。
- DDC IIC信号经过TMDS181芯片转接，
  R247、R387、R245、R243 NC，R248、R244、R249、R246上件
  DDC IIC信号不经过TMDS181芯片转接，
  R248、R244、R249、R246 NC，R247、R387、R245、R243 NC
sheet 3
- HDMI OUT3
- 差分信号的输入端是否加电容
  输出端是否加电感
- 电源去耦电容
- TMDS181配置管脚
- 5V输出限流
- 5V电源输出限流+防倒灌，limit（A）=6800/Rocb
- TMDS181芯片配置：I2C控制模式
- DDC输出选择
- HPD接入选择
- HPD信号经过TMDS181芯片转接，R392上件，R393 NC
  HPD信号直接由FPGA控制，R393上件，R392 NC
- DDCI2C 可选择接入TMDS181的SRC_I2C（默认）
  或者 直接接到PCA9306DC1A的I2C输入接口。
- DDC IIC信号经过TMDS181芯片转接，
  R247、R387、R245、R243 NC，R248、R244、R249、R246上件
  DDC IIC信号不经过TMDS181芯片转接，
  R248、R244、R249、R246 NC，R247、R387、R245、R243 NC
sheet 5
- 1. 25Mhz无源晶体
  2. 25Mhz有源晶振
  Si5338A输入时钟可选，未使
  用的时钟输入管脚需接地。
- 1. 25Mhz无源晶体
  2. 25Mhz有源晶振
  Si5338A输入时钟可选，未使
  用的时钟输入管脚需接地。
